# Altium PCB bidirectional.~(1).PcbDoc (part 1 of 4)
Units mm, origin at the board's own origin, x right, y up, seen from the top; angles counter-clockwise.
Board outline 190.5 x 127 mm, 6 copper layers (Top Layer, MidLayer1, MidLayer2, Mid-Layer 3, Mid-Layer 4, Bottom Layer), stack 2.997 mm thick; 416 components, 178 nets, 1084 pads, 2010 vias.
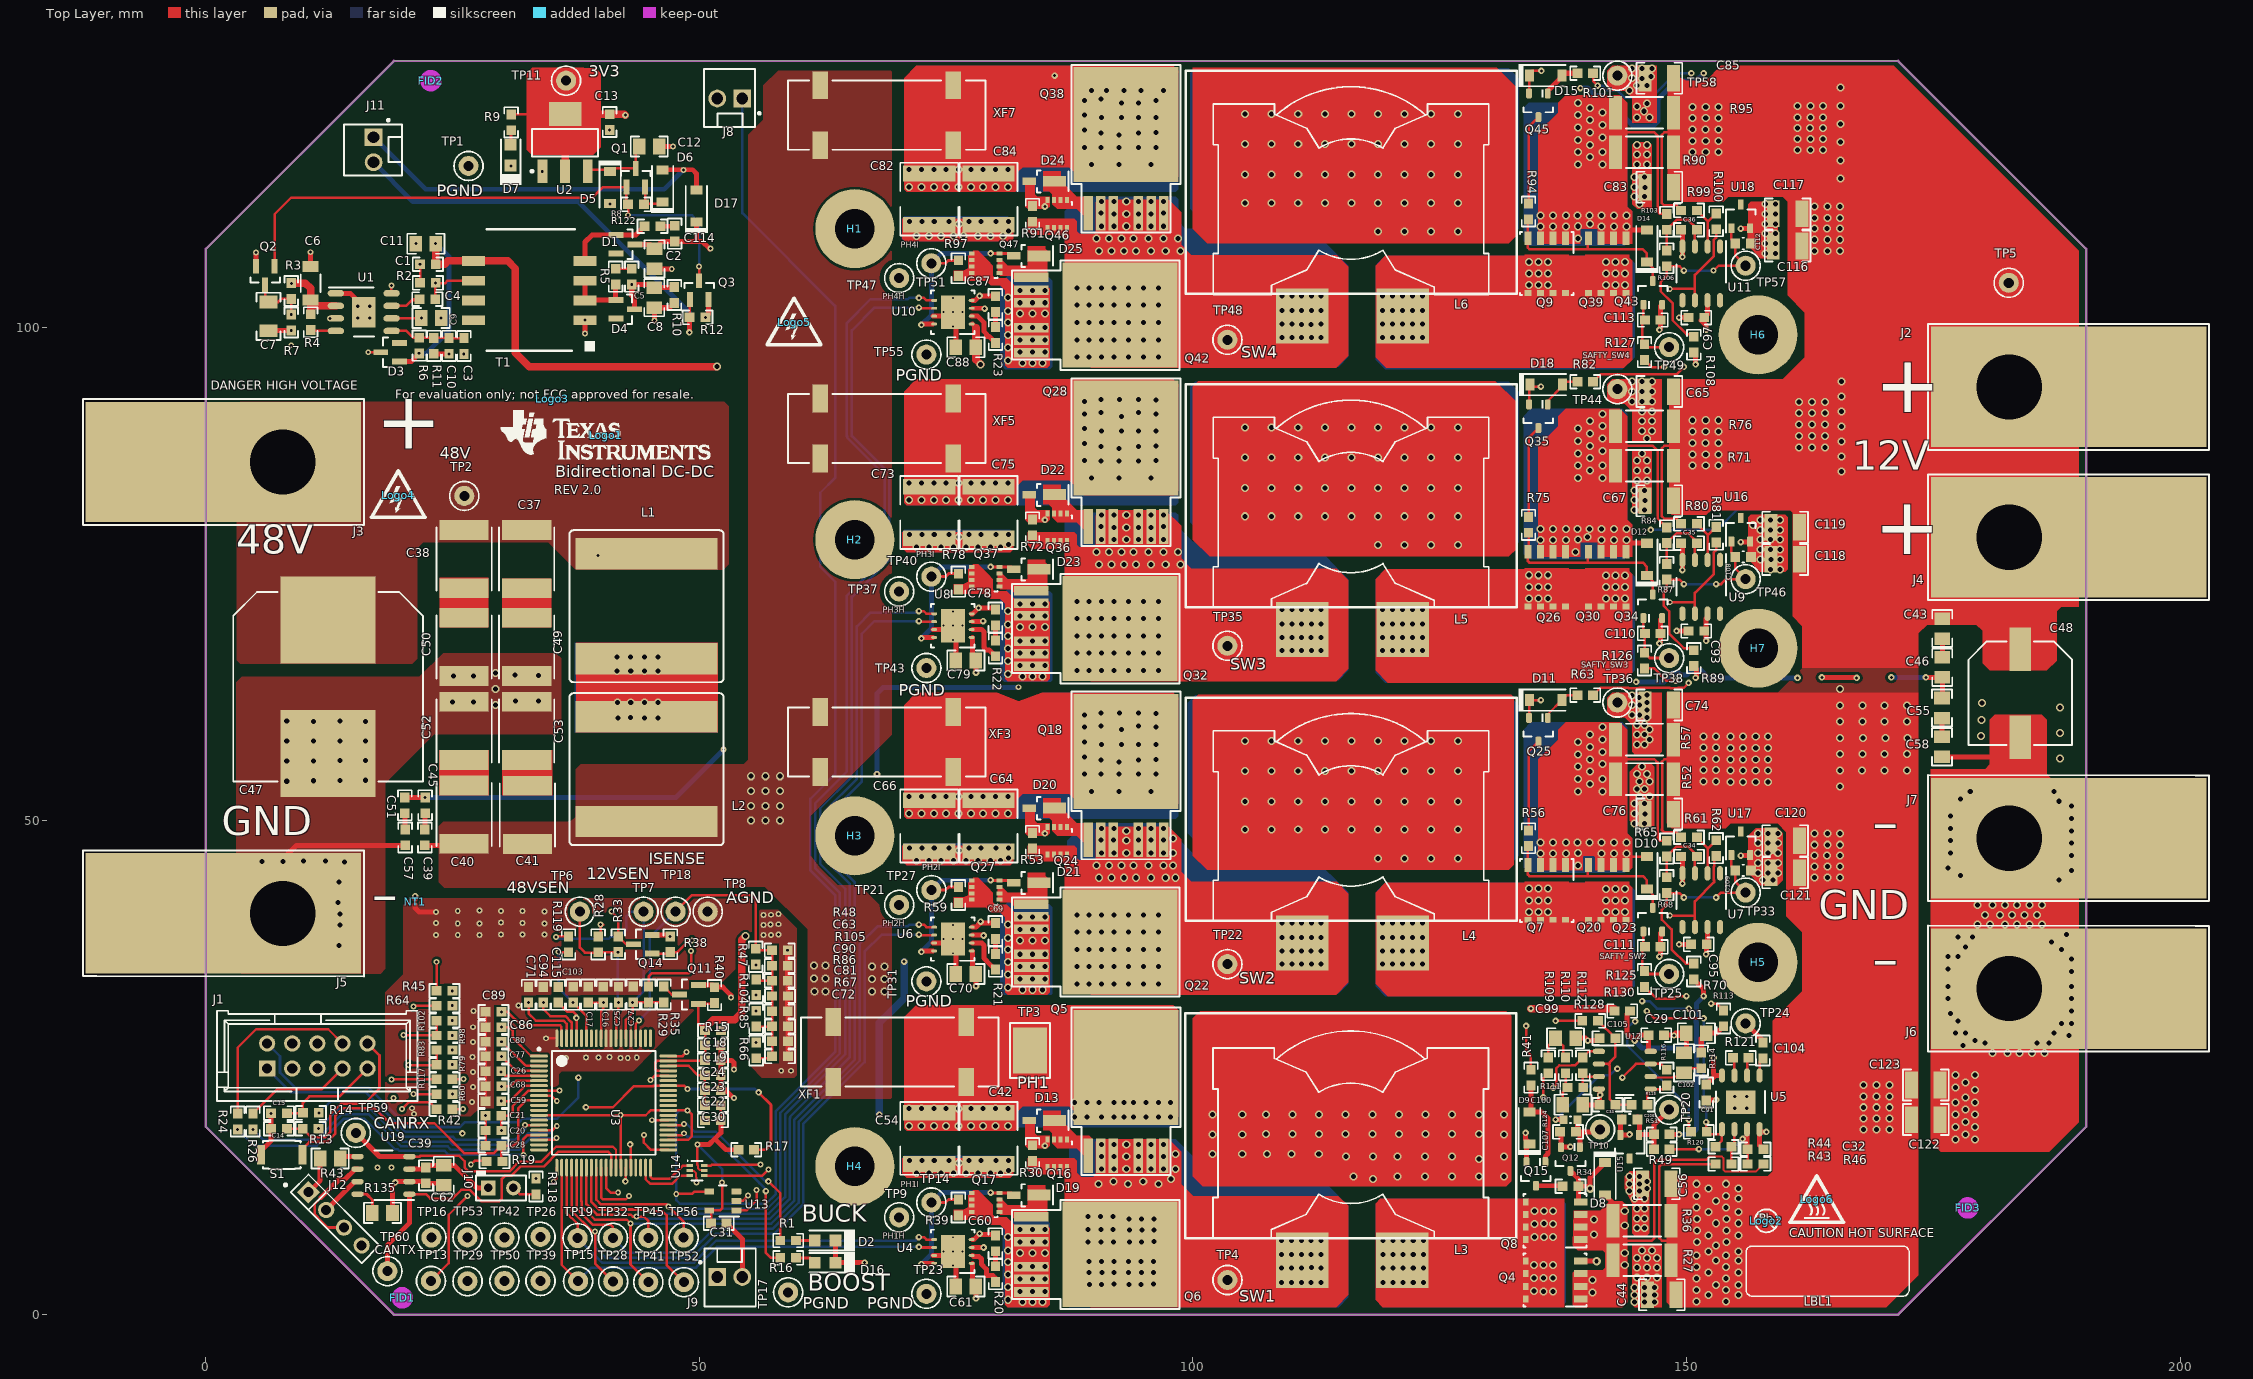
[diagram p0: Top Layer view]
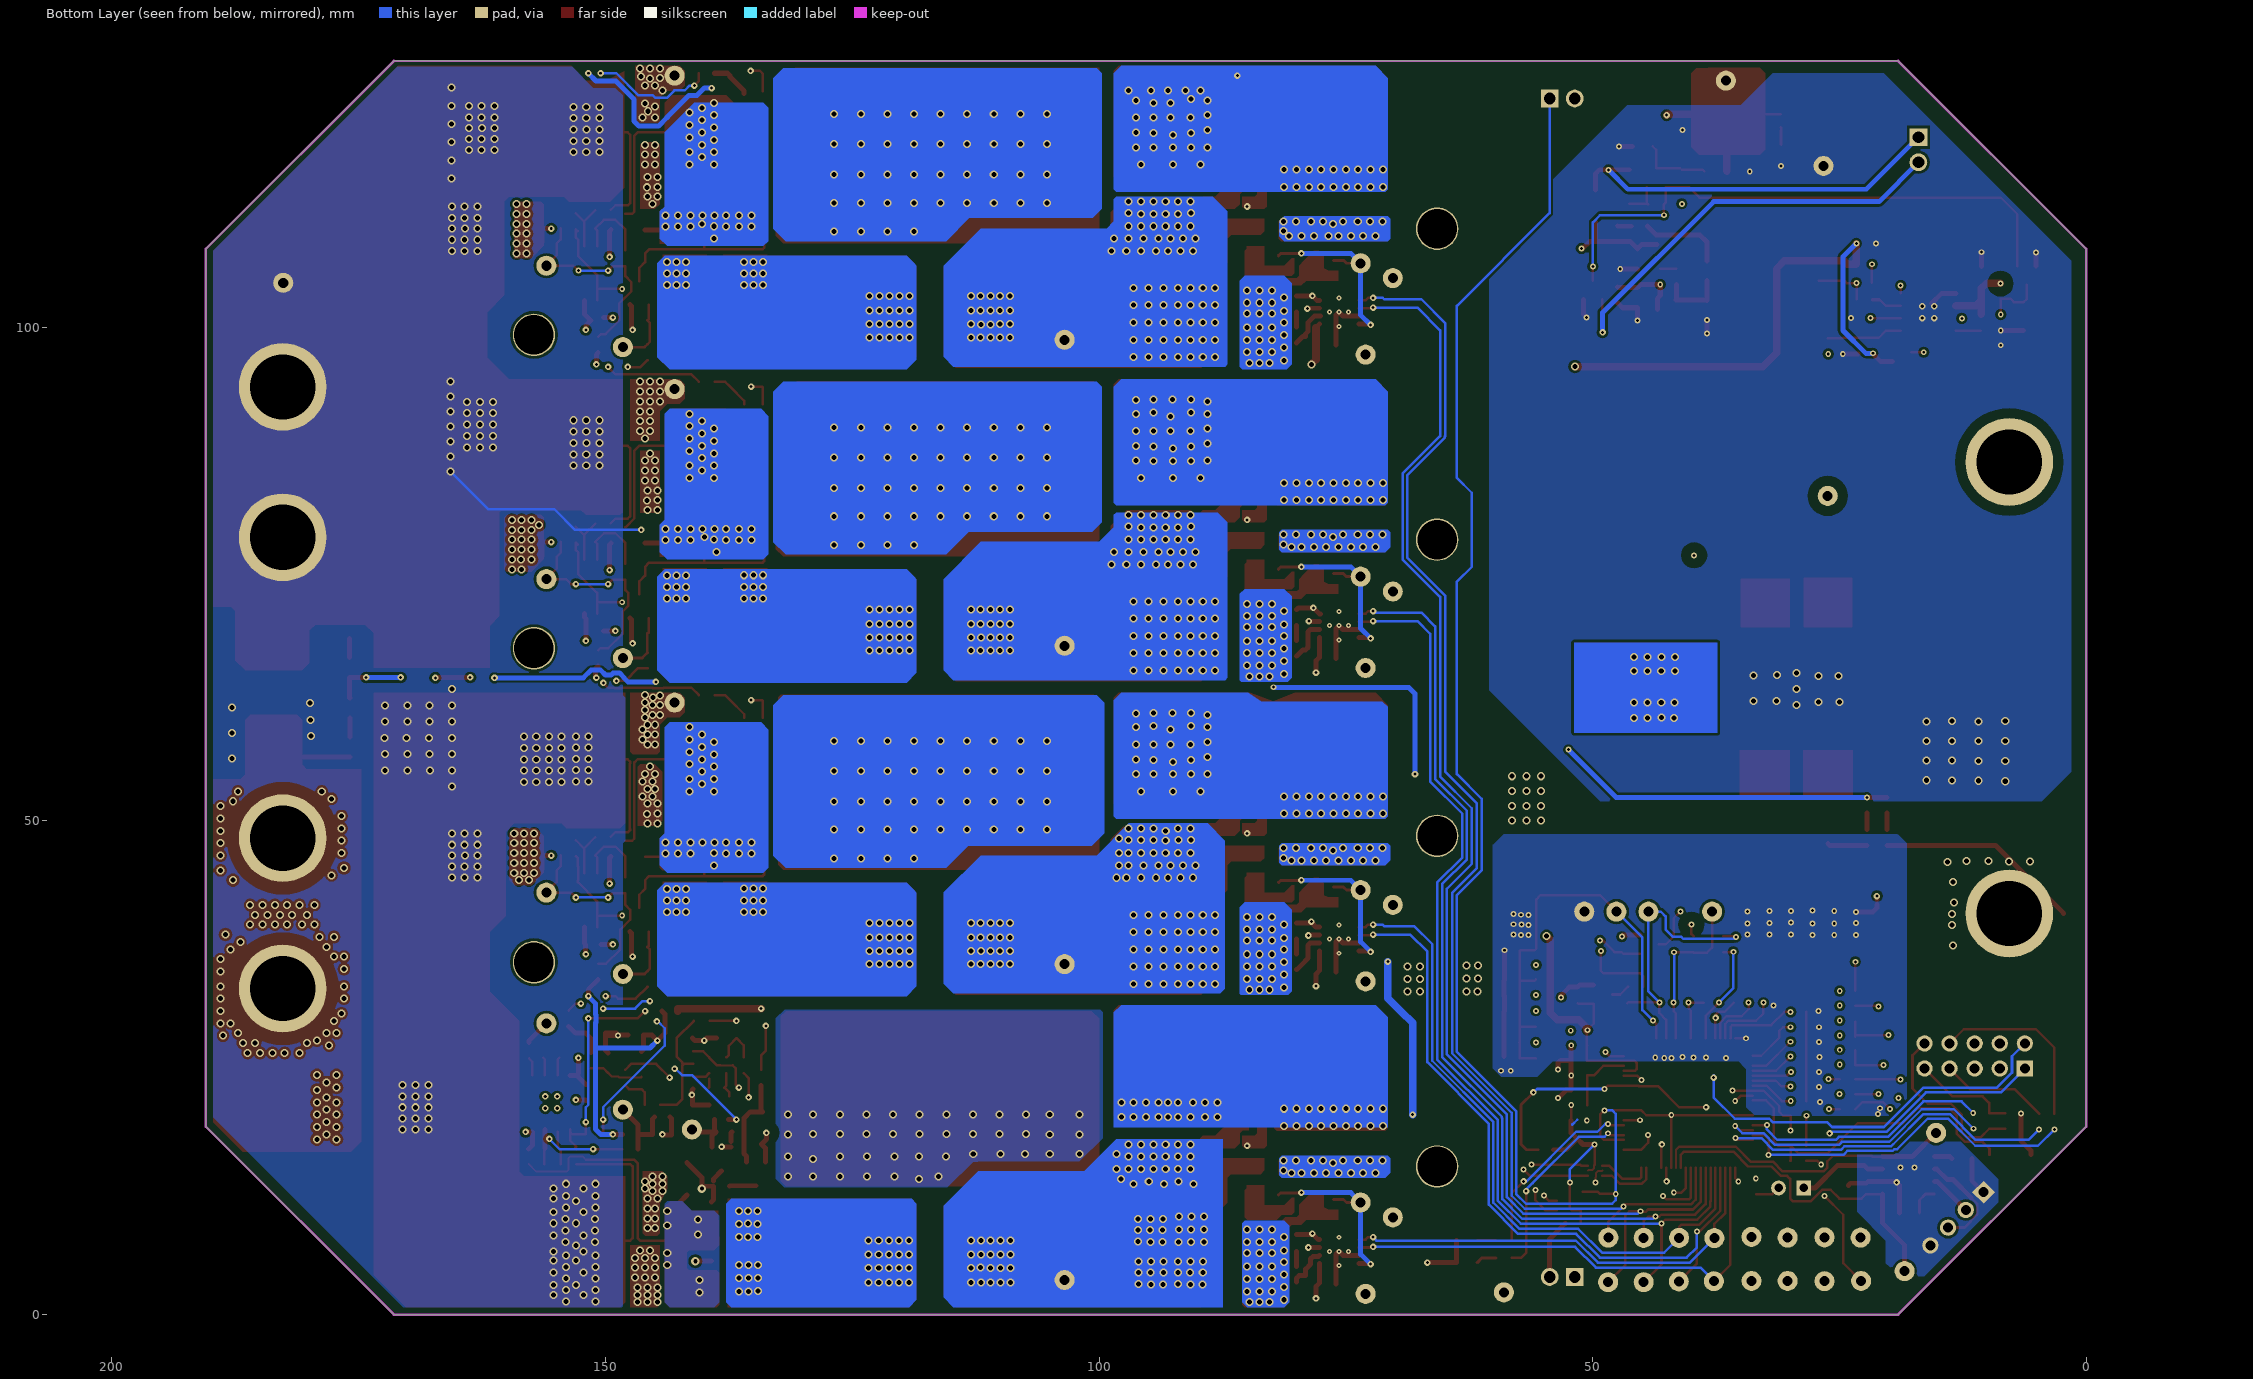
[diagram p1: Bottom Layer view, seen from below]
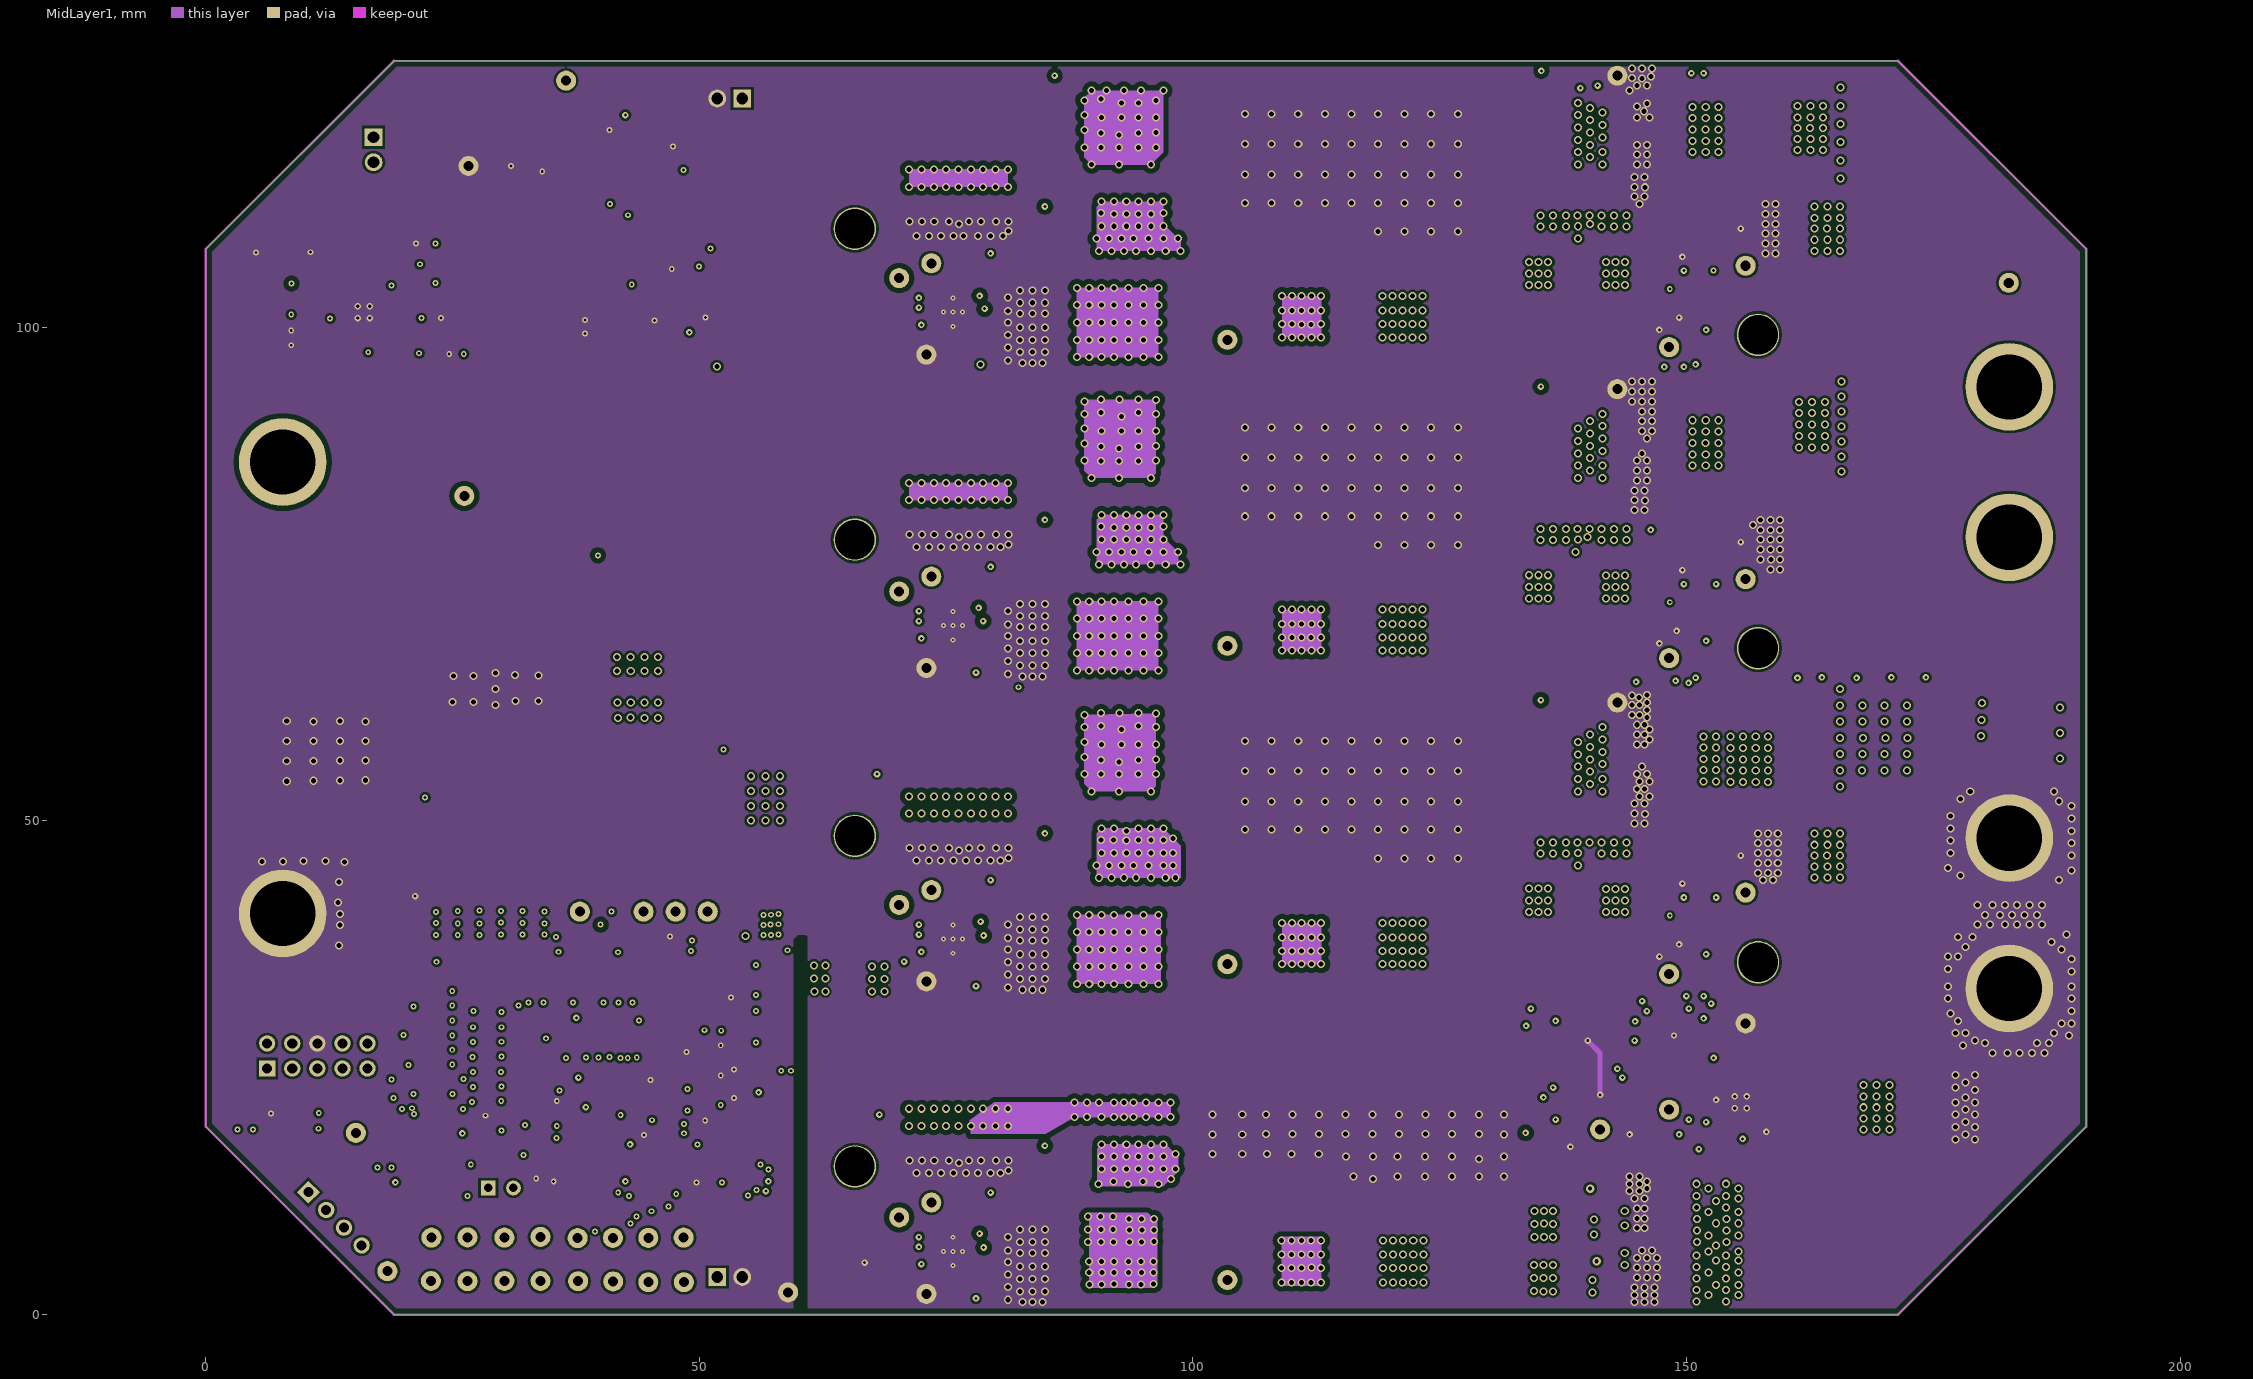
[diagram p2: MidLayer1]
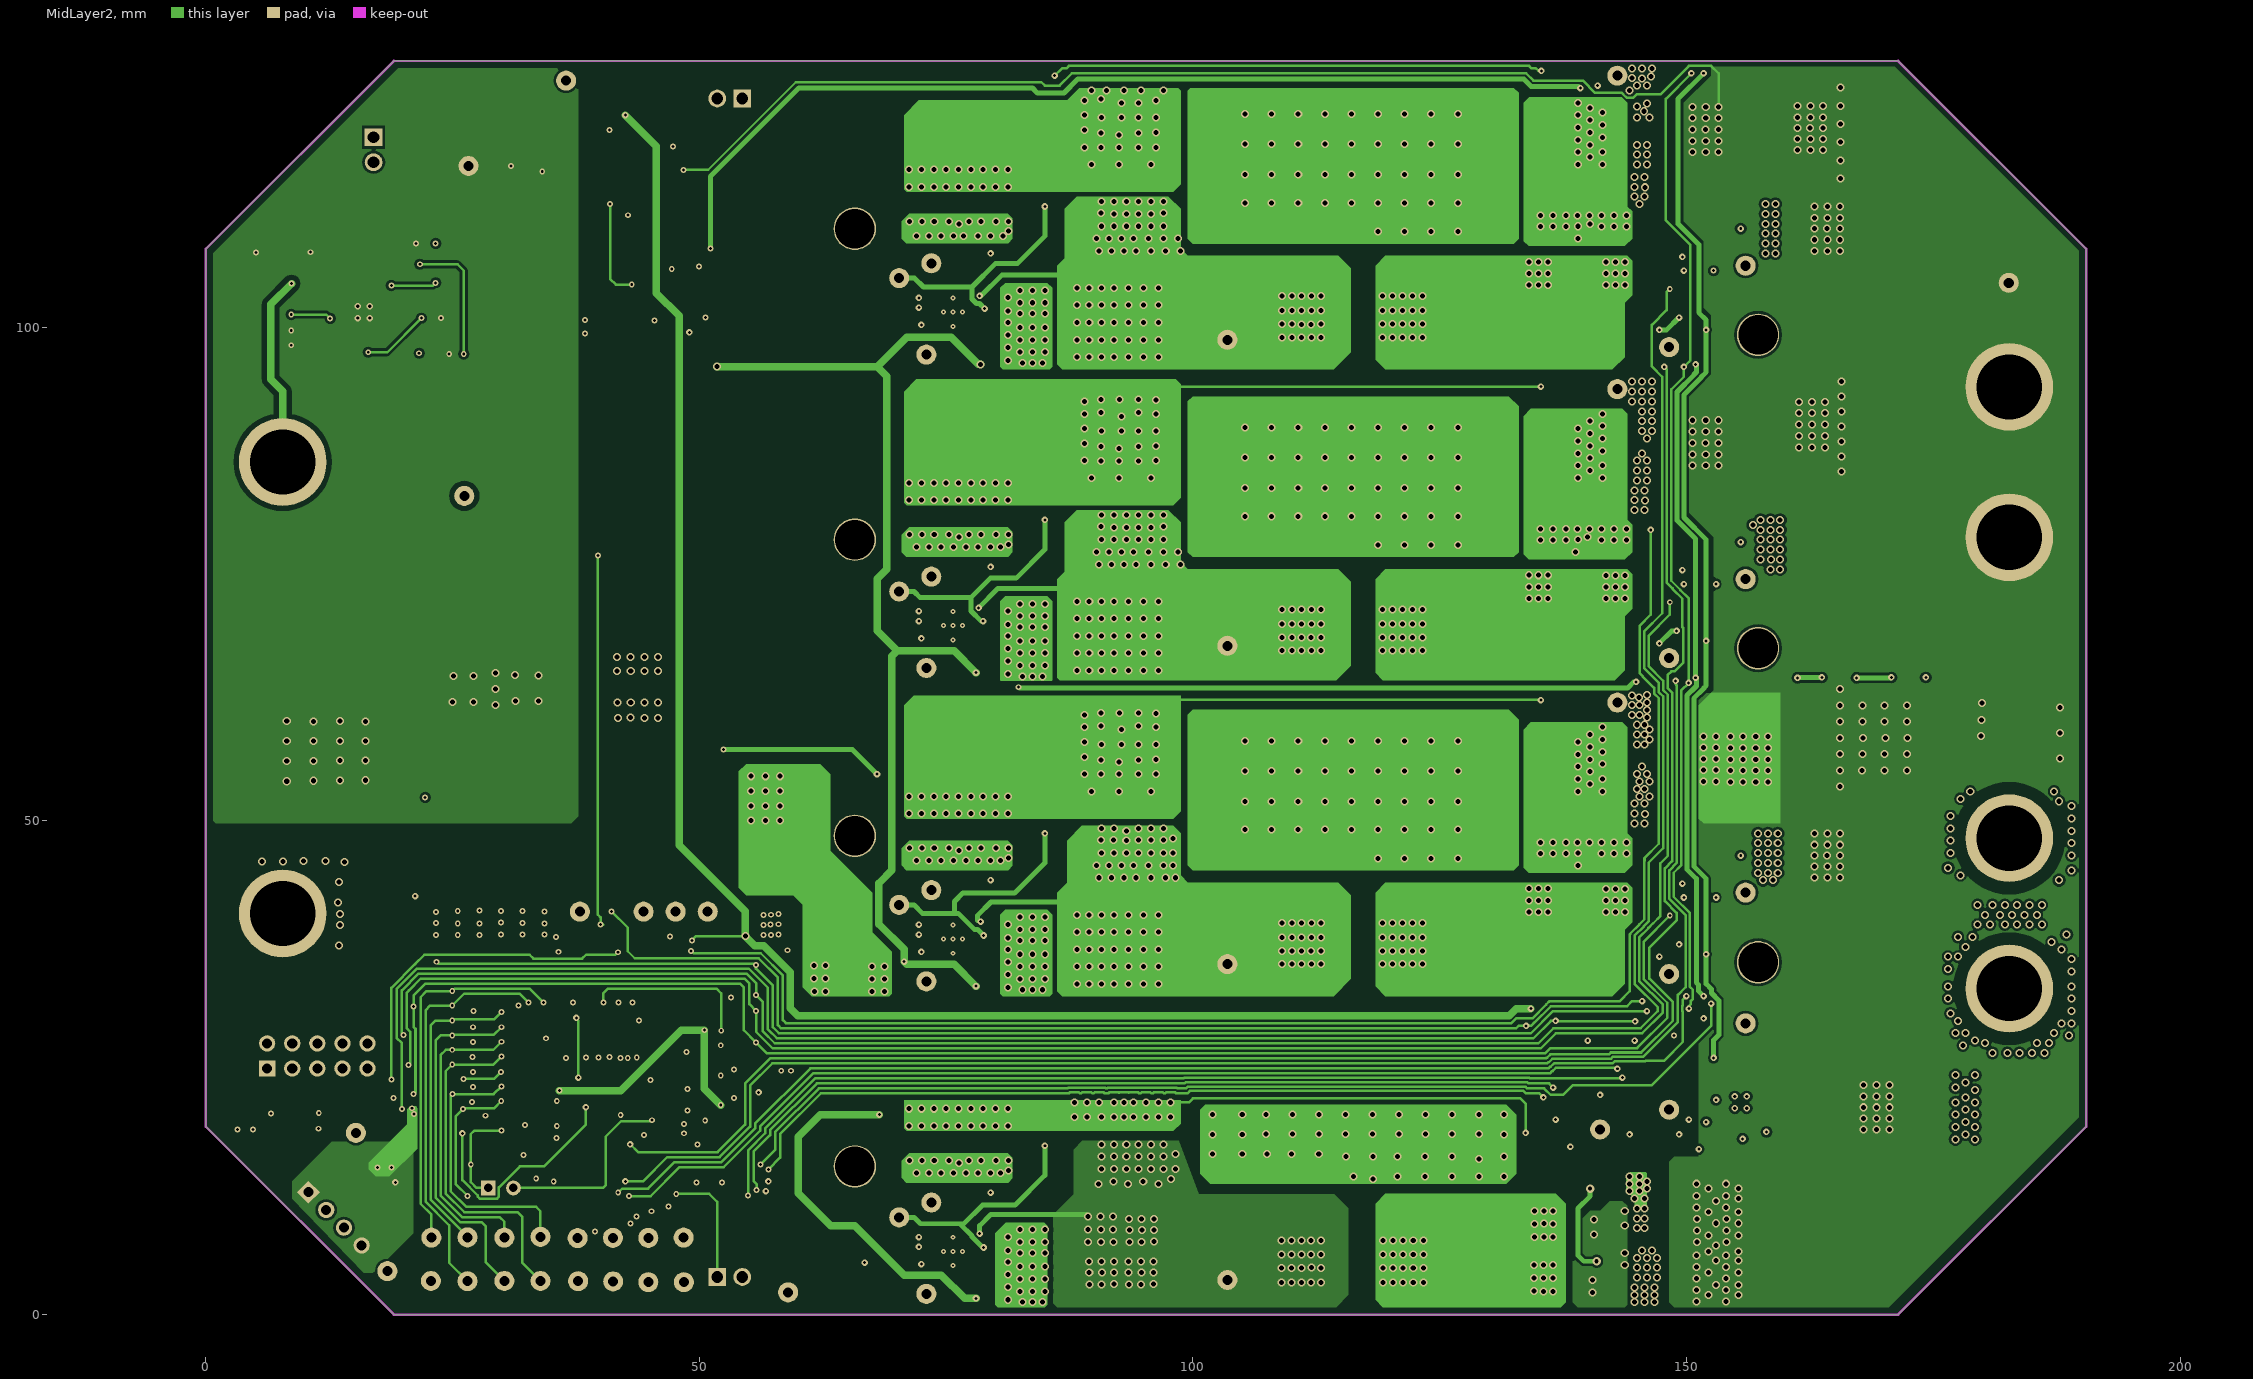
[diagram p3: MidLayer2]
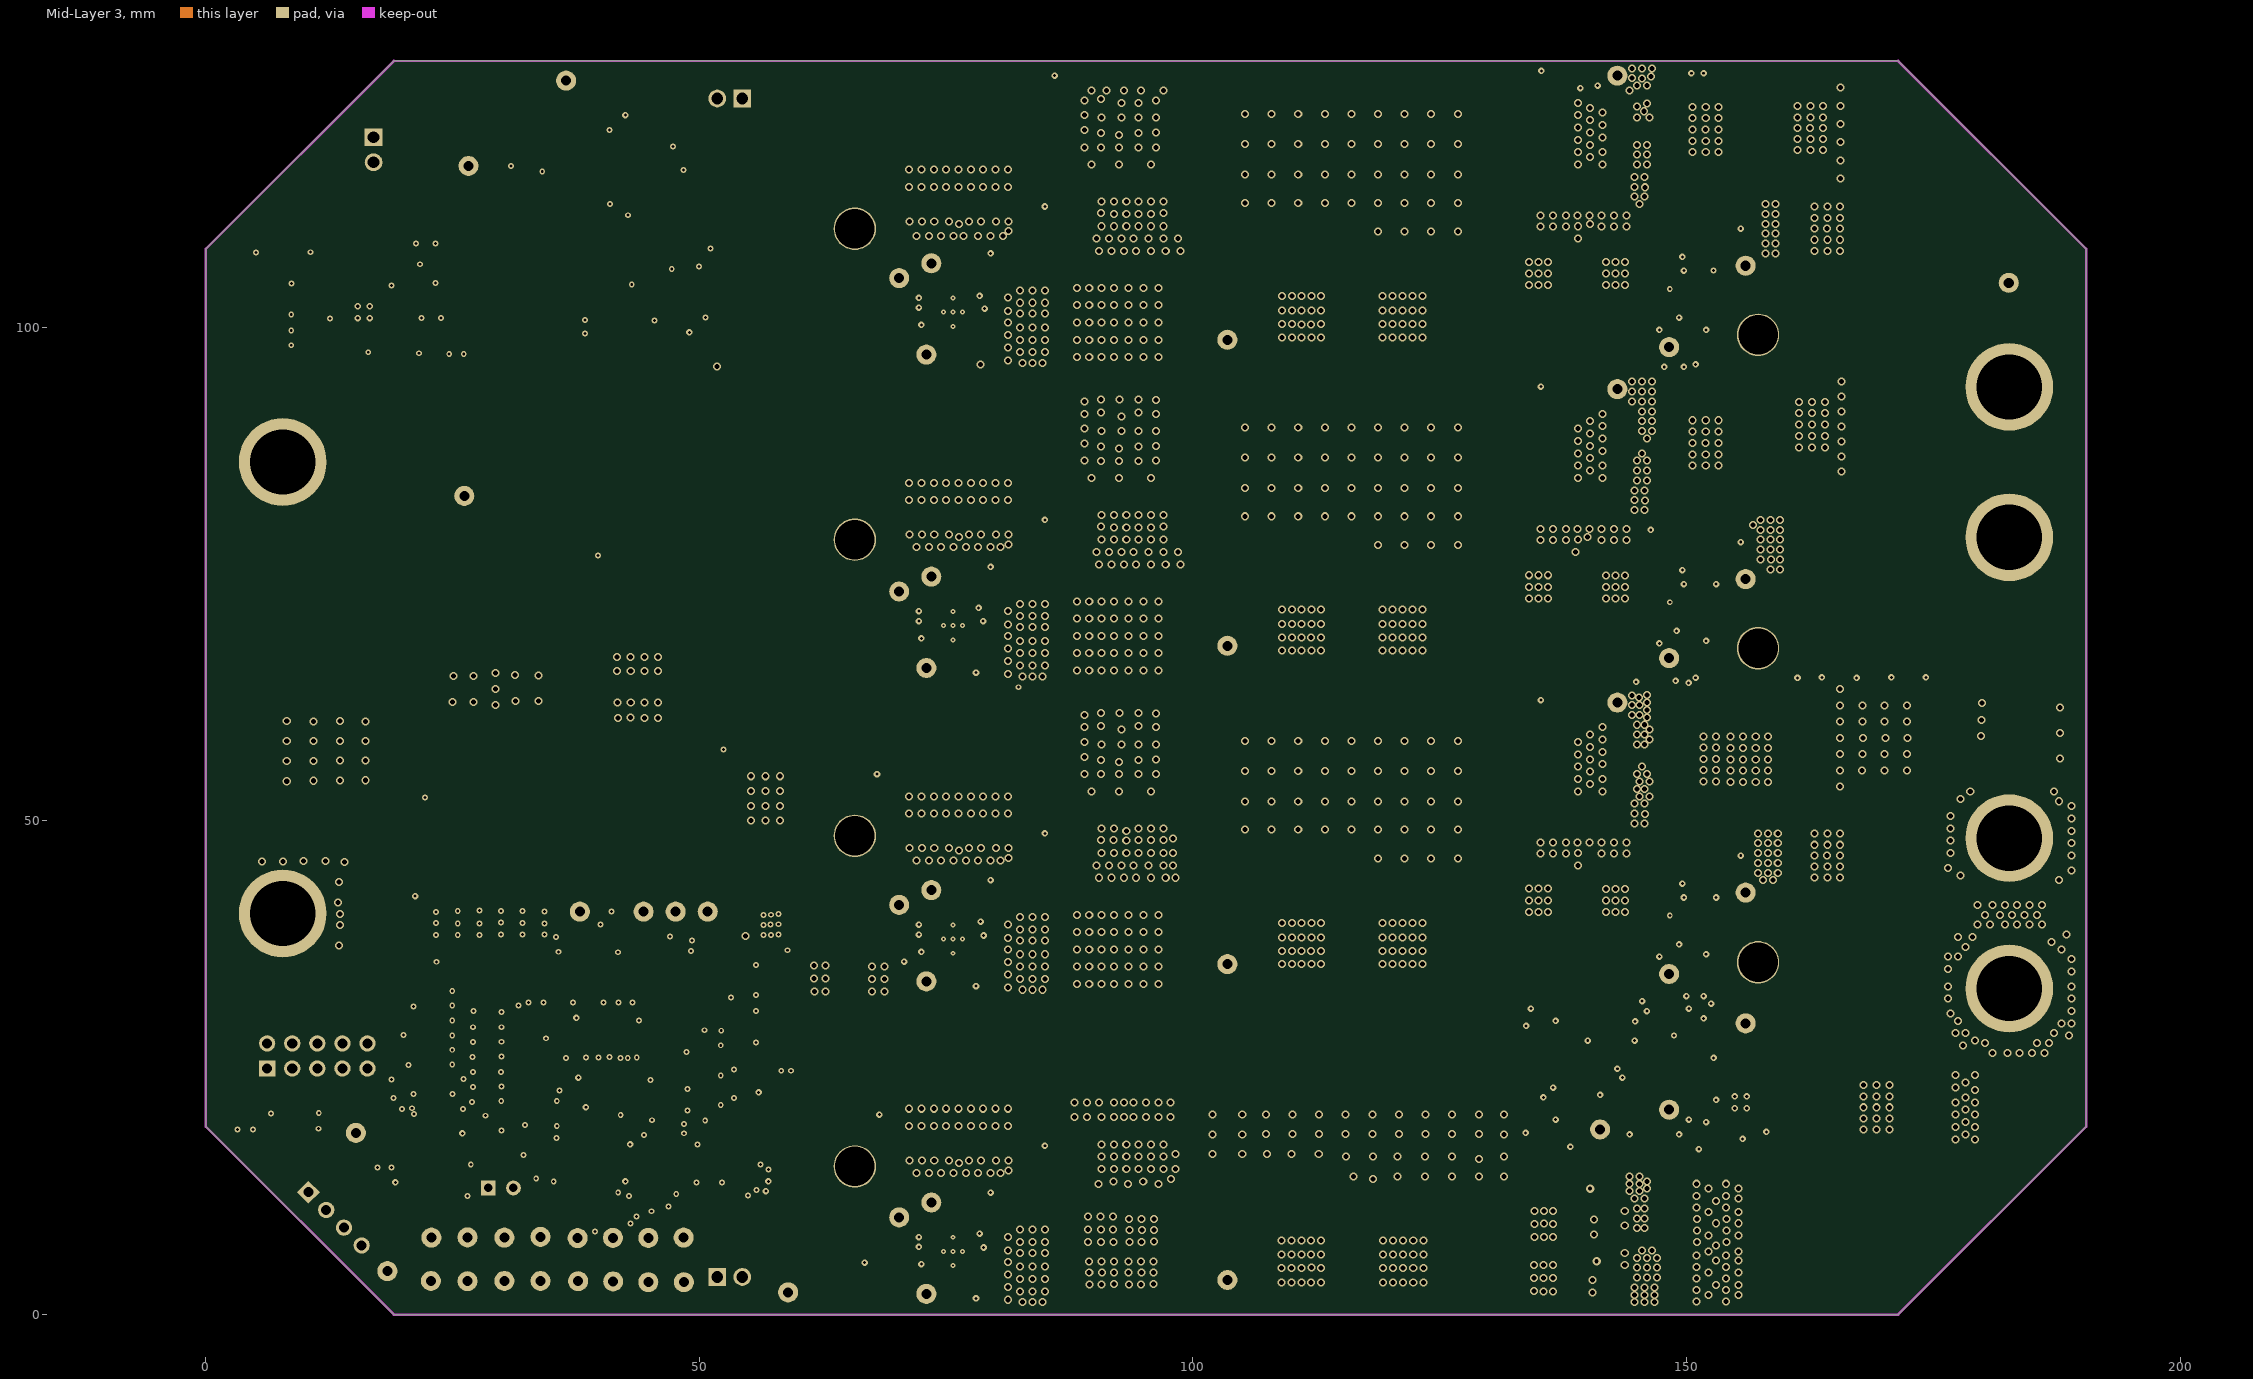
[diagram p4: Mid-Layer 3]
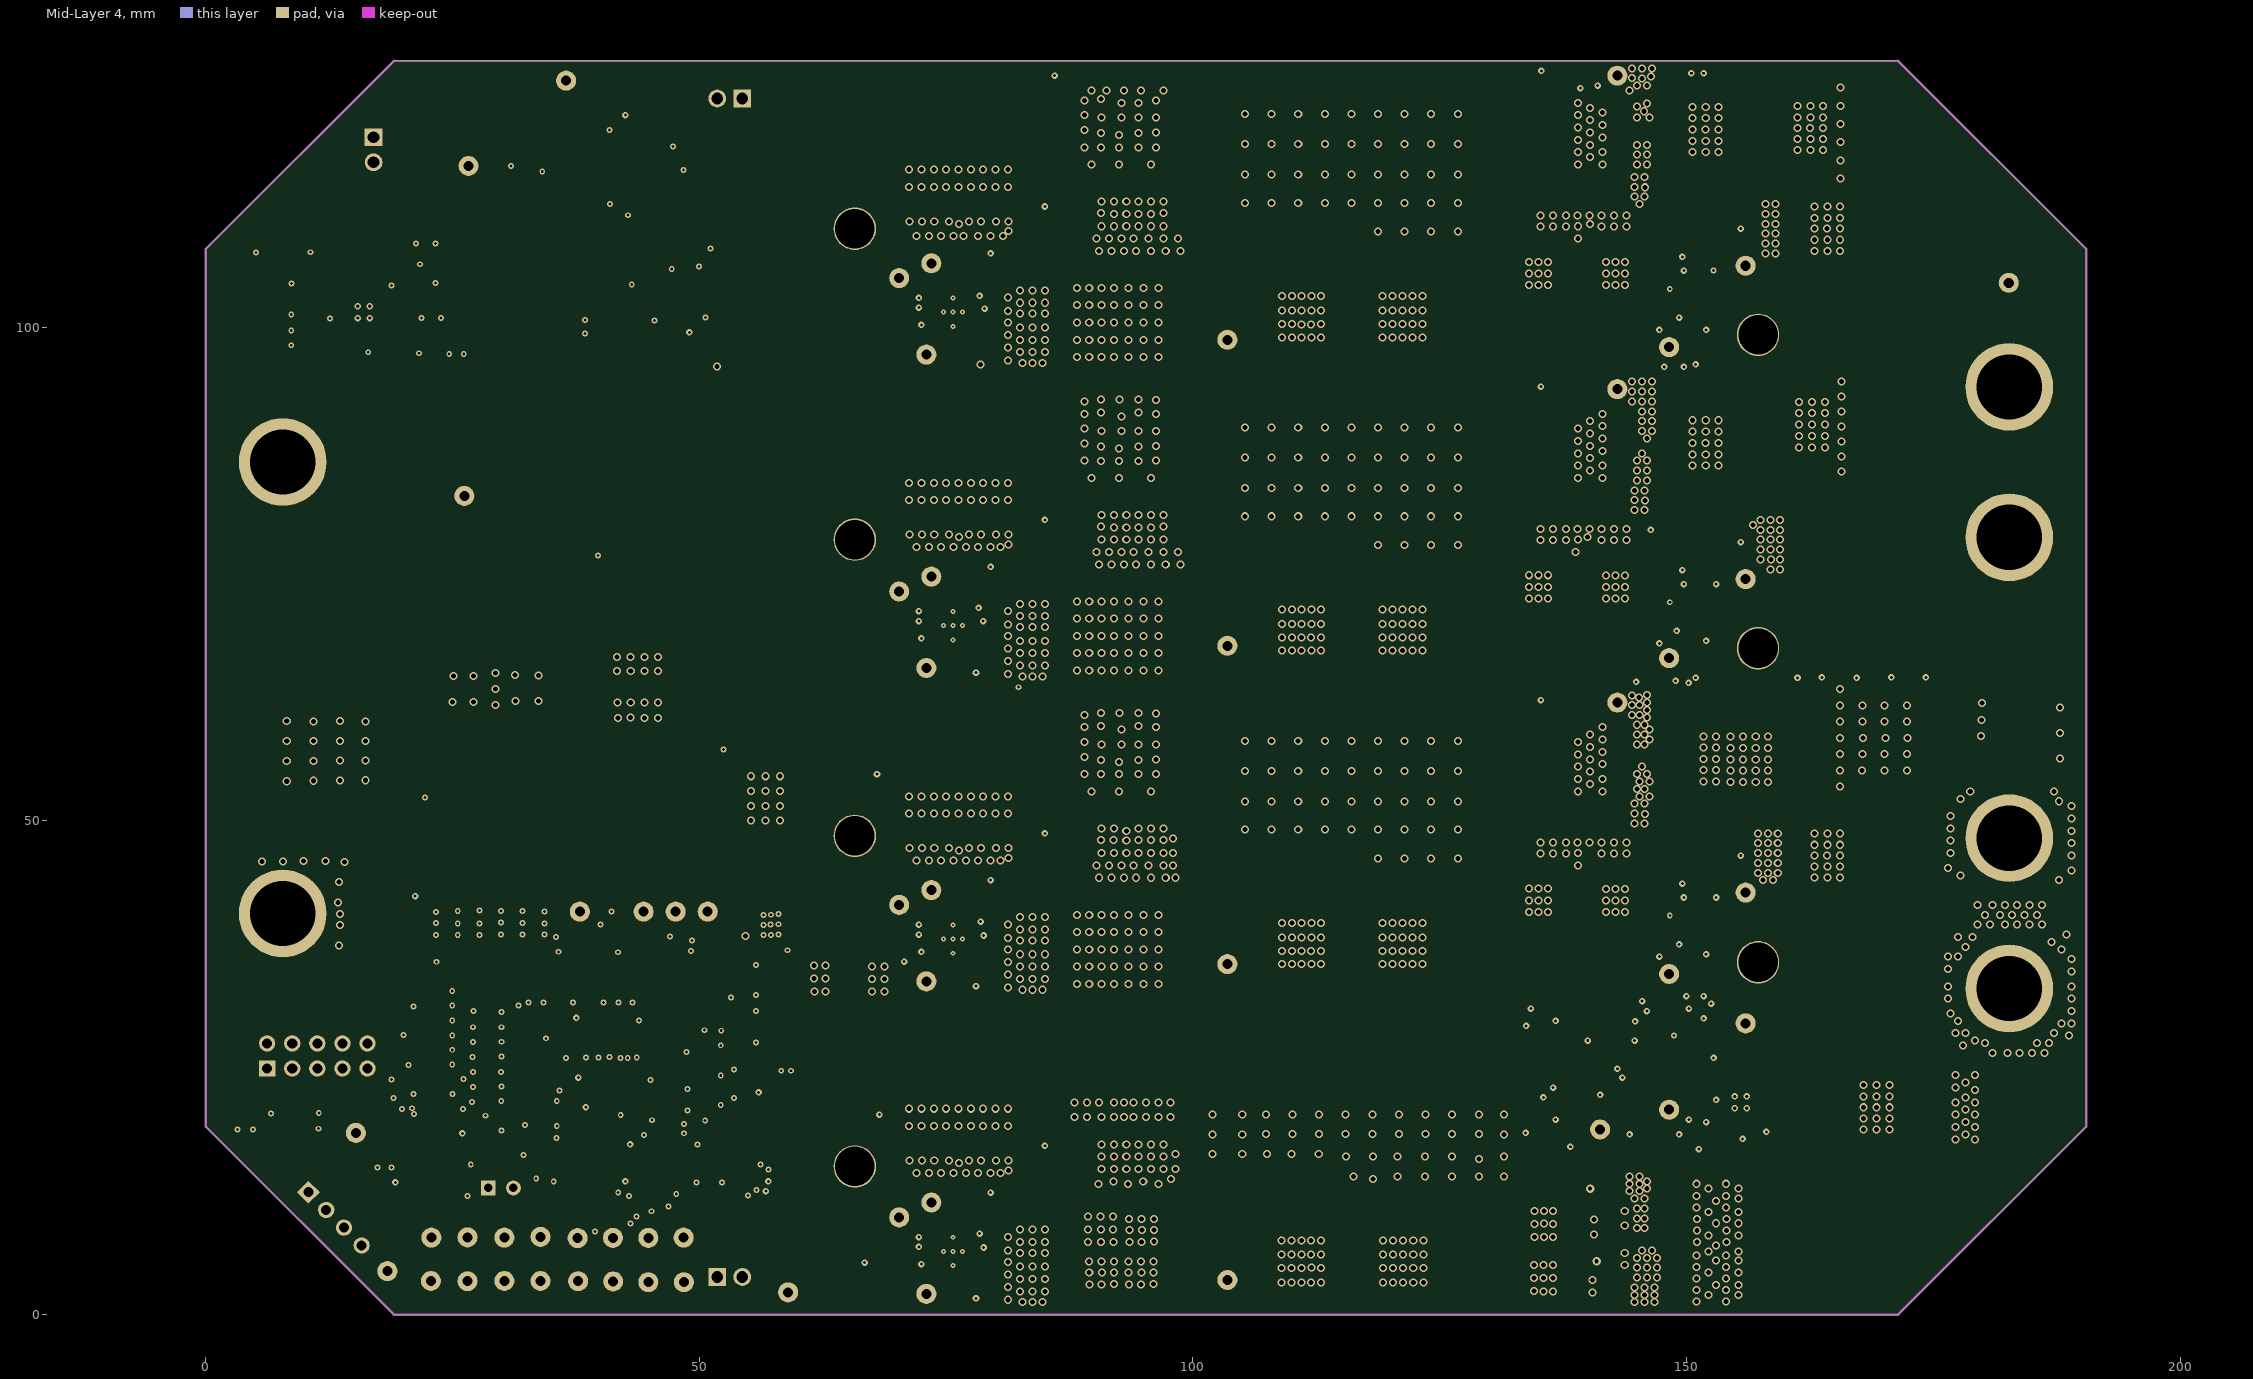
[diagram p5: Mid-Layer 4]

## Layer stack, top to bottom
Top Solder: solder mask 0.0102, Solder Resist, Dk 3.5
Top Layer: signal copper 0.0356
Dielectric1: core 1.5037, FR-4, Dk 4.8
MidLayer1: signal copper 0.0356
Dielectric2: prepreg 0.32, FR-4, Dk 4.8
MidLayer2: signal copper 0.0356
Dielectric3: core 0.32, FR-4, Dk 4.8
Mid-Layer 3: signal copper 0.0356
Dielectric4: dielectric 0.32, FR-4, Dk 4.8
Mid-Layer 4: signal copper 0.0356
Dielectric5: dielectric 0.32, FR-4, Dk 4.8
Bottom Layer: signal copper 0.0356
Bottom Solder: solder mask 0.0102, Solder Resist, Dk 3.5

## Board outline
0,19.05 19.05,0 171.45,0 190.5,19.05 190.5,107.95 171.45,127 19.05,127 0,107.95

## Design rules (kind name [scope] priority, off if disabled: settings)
AcuteAngle [All] p1 off: minimum=4.50000000000000E+0001 checktracksonly=FALSE
AssemblyTestPointUsage [All] p1 off: valid=2
AssemblyTestpoint [All] p1 off: testpointundercomponent=TRUE minsize=1.016 maxsize=2.54 preferedsize=1.524 minholesize=0 maxholesize=1.016 preferedholesize=0.813 testpointgrid=0.025 usegrid=TRUE gridtolerance=0 allowsidetop=TRUE allowsidebottom=TRUE
Clearance "1. HVvPGND Objs on Multilayer" [InNetClass('HV') And OnMultiLayer vs Not InNetClass('HV') And OnMultiLayer] p1: gap=1
Clearance "2a. HVvPGND Objs on Top" [InNetClass('HV') And OnTopLayer vs Not InNetClass('HV') And (OnTopLayer Or OnMultiLayer)] p2: gap=1
Clearance "2b. HVvPGND Objs on Bottom" [InNetClass('HV') And OnBottomLayer vs Not InNetClass('HV') And (OnBottomLayer Or OnMultiLayer)] p3: gap=1
Clearance "3a. HVvPGND Objs on Top" [Not InNetClass('HV') And OnTopLayer vs InNetClass('HV') And (OnTopLayer Or OnMultiLayer)] p4: gap=1
Clearance "3b. HVvPGND Objs on Bottom" [Not InNetClass('HV') And OnBottomLayer vs InNetClass('HV') And (OnBottomLayer Or OnMultiLayer)] p5: gap=1
Clearance "4. HVvPGND  Objs on Mid" [InNetClass('HV') And OnMid vs Not InNetClass('HV') And (OnMid Or OnMultiLayer)] p6: gap=0.5
Clearance "5. HVvPGND Objs on Mid" [Not InNetClass('HV') And OnMid vs InNetClass('HV') And (OnMid Or OnMultiLayer)] p7: gap=0.5
Clearance Clearance_BoardEdge_MountingHoles [OnCopper and InComponentClass('Mounting Holes') vs IsKeepOut] p8: gap=1.016
Clearance Clearance_BoardEdge_Poly [OnCopper and InPoly vs OnLayer('Keep-Out Layer')] p9: gap=0.5
Clearance Clearance_Poly [InPolygon] p10: gap=0.25
Clearance [OnCopper vs OnCopper] p11: gap=0.199
ComponentClearance ComponentClearance_Shunt [InComponentClass('Header') vs InComponentClass('Shunt')] p1: gap=0 collisioncheckmode=3 verticalgap=0 showdistances=FALSE
ComponentClearance ComponentClearance_Logo [InComponentClass('Logo')] p2: gap=0.25 collisioncheckmode=3 verticalgap=0 showdistances=FALSE
ComponentClearance ComponentClearance_ScrewToNut [(HasFootprint('NY PMS 440 0025 PH')) vs (HasFootprint('Keystone_1902C'))] p3: gap=0.127 collisioncheckmode=3 verticalgap=0.254 showdistances=FALSE
ComponentClearance ComponentClearance_MountingHoles [InComponentClass('Mounting Holes')] p4: gap=0.1 collisioncheckmode=3 verticalgap=0 showdistances=FALSE
ComponentClearance ComponentClearance_SmallPassives [HasFootprint('0201*') or HasFootprint('0402*') or HasFootprint('0508') or HasFootprint('0603*') or HasFootprint('0612') or HasFootprint('0805*') or HasFootprint('0815*') or HasFootprint('0830*') or HasFootprint('1206*') or HasFootprint('1210*') or HasFootprint('1808*') or HasFootprint('1812*') or HasFootprint('1825*') or HasFootprint('2010*') or HasFootprint('2220*') or HasFootprint('2225*') or HasFootprint('2512*') or HasFootprint('2728*') or HasFootprint('3518*') vs HasFootprint('0201*') or HasFootprint('0402*') or HasFootprint('0508') or HasFootprint('0603*') or HasFootprint('0612') or HasFootprint('0805*') or HasFootprint('0815*') or HasFootprint('0830*') or HasFootprint('1206*') or HasFootprint('1210*') or HasFootprint('1808*') or HasFootprint('1812*') or HasFootprint('1825*') or HasFootprint('2010*') or HasFootprint('2220*') or HasFootprint('2225*') or HasFootprint('2512*') or HasFootprint('2728*') or HasFootprint('3518*')] p5: gap=0.05 collisioncheckmode=3 verticalgap=0.02 showdistances=FALSE
ComponentClearance ComponentClearance_THtoSMT [IsThruComponent vs IsSMTComponent] p6: gap=0.1 collisioncheckmode=3 verticalgap=0.1 showdistances=FALSE
ComponentClearance ComponentClearance_THtoTH [IsThruComponent vs IsThruComponent] p7: gap=0.1 collisioncheckmode=3 verticalgap=0.1 showdistances=FALSE
ComponentClearance [All] p8: gap=0.05 collisioncheckmode=3 verticalgap=0 showdistances=FALSE
DiffPairsRouting [All] p1 off: maxlimit=2.54 minlimit=0.254 mostfreqgap=0.254 toplayer_minwidth=0.381 toplayer_maxwidth=0.381 toplayer_prefwidth=0.381 midlayer1_minwidth=0.381 midlayer1_maxwidth=0.381 midlayer1_prefwidth=0.381 midlayer2_minwidth=0.381 midlayer2_maxwidth=0.381 midlayer2_prefwidth=0.381 midlayer3_minwidth=0.381 midlayer3_maxwidth=0.381 midlayer3_prefwidth=0.381 midlayer4_minwidth=0.381 midlayer4_maxwidth=0.381 midlayer4_prefwidth=0.381 bottomlayer_minwidth=0.381 bottomlayer_maxwidth=0.381 bottomlayer_prefwidth=0.381 maxuncoupledlength=25.4
FabricationTestPointUsage TestPointUsage [All] p1 off: valid=2 allowmultiple=FALSE
FabricationTestpoint Testpoint [All] p1 off: side=3 testpointundercomponent=TRUE minsize=1.016 maxsize=2.54 preferedsize=1.524 minholesize=0 maxholesize=1.016 preferedholesize=0.813 testpointgrid=0.025 allowsidetop=TRUE allowsidebottom=TRUE usegrid=TRUE gridtolerance=0
FanoutControl Fanout_LCC [IsLCC] p1 off: bgadir=Out bgaviamode=Centered fanoutstyle=Auto fanoutdirection=Alternating viagrid=0.025 // Fanout_LCC (Default Rule)
FanoutControl Fanout_BGA [IsBGA] p2 off: bgadir=Out bgaviamode=Centered fanoutstyle=Auto fanoutdirection=Alternating viagrid=0.025 // Fanout_BGA (Default Rule)
FanoutControl Fanout_SOIC [IsSOIC] p3 off: bgadir=Out bgaviamode=Centered fanoutstyle=Auto fanoutdirection=Alternating viagrid=0.025 // Fanout_SOIC (Default Rule)
FanoutControl Fanout_Default [All] p4 off: bgadir=Out bgaviamode=Centered fanoutstyle=Auto fanoutdirection=Alternating viagrid=0.025 // Fanout_Default (Default Rule)
FanoutControl Fanout_Small [(CompPinCount < 5)] p5 off: bgadir=Out bgaviamode=Centered fanoutstyle=Auto fanoutdirection=OutThenIn viagrid=0.025 // Fanout_Small (Default Rule)
Height [All] p1 off: minheight=0 maxheight=25.4 prefheight=12.7
HoleSize [All] p1: absolutevalues=TRUE maxlimit=7 minlimit=0.2 maxpercent=80.000 minpercent=20.000
HoleToHoleClearance [All] p1: gap=0.199 allowstackedmicrovias=TRUE
LayerPairs [All] p1 off: enforce=TRUE
MinimumAnnularRing MinimumAnnularRing_ThermalPadVias [IsVia and InAnyComponent] p1: minimumring=0.149
MinimumAnnularRing [All] p2: minimumring=0.149
MinimumSolderMaskSliver MinimumSolderMaskSliver_Logo [InComponentClass('Logo') vs InComponentClass('Logo')] p1: minsoldermaskwidth=0.018
MinimumSolderMaskSliver [All] p2 off: minsoldermaskwidth=0.04
PlaneClearance [All] p1 off: clearance=0.381
PlaneConnect PlaneConnect_1 [All] p1 off: planeconnectstyle=Direct reliefexpansion=0.508 reliefentries=4 reliefconductorwidth=0.254 reliefairgap=0.254
PlaneConnect [ISVIA] p2 off: planeconnectstyle=Direct reliefexpansion=0.254 reliefentries=4 reliefconductorwidth=0.254 reliefairgap=0.254
PolygonConnect PolygonConnect_1 [All vs isvia] p1: connectstyle=Direct reliefconductorwidth=0.254 reliefentries=4 polygonreliefangle="90 Angle" airgapwidth=0.254
PolygonConnect [All] p2: connectstyle=Direct reliefconductorwidth=0.254 reliefentries=4 polygonreliefangle="90 Angle" airgapwidth=0.254
RoutingLayers [All] p1 off: top layer_v5=TRUE mid layer 1_v5=TRUE mid layer 2_v5=TRUE mid layer 3_v5=FALSE mid layer 4_v5=FALSE bottom layer_v5=TRUE
RoutingPriority [All] p1 off: routingpriority=0
RoutingTopology [All] p1 off: topology=Shortest
RoutingVias [All] p1: holewidth=0.3 width=0.6 viastyle="Through Hole" minholewidth=0.2 minwidth=0 maxholewidth=1 maxwidth=1.5
SilkToBoardRegionClearance [All] p1 off:
SilkToSilkClearance [All] p1: silktosilkclearance=0
SilkToSolderMaskClearance SilkscreenOverComponentPads [IsPad] p1: minsilkscreentomaskgap=0 clearancetoexposedcopper=TRUE
SolderMaskExpansion [All] p1: expansion=0.05
UnpouredPolygon [All] p1: allowunpoured=FALSE
Width [All] p1: maxlimit=2.54 minlimit=0.2 preferedwidth=0.5 checkconnectedcopper=TRUE
5 further rules are at their usual default settings.

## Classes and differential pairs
net class HV: BAT_48V NetD13_1 NetD20_1 NetD22_1 NetD24_1 PH1_H PH2_H PH3_H PH4_H PHASE1 PHASE2 PHASE3 PHASE4 SW1 SW2 SW3 SW4
component class "Aux Power Supply": C1 C2 C3 C4 C5 C6 C7 C8 C9 C10 C11 C12 C13 C114 D1 D3 D4 D5 D6 D7 D17 J11 Q1 Q2 Q3 R2 R3 R4 R5 R6 R7 R8 R9 R10 R11 R12 R122 T1 TP1 U1 U2
component class bidirectional-MCU: C14 C15 C16 C17 C18 C19 C20 C21 C22 C23 C24 C25 C26 C27 C28 C39 C62 C103 C115 D2 D16 J1 J8 J9 J10 J12 NT1 R1 R13 R14 R15 R16 R17 R19 R24 R26 R43 R117 R118 R119 R124 R125 R126 R127 R135 S1 TP8 TP17 TP59 TP60 U3 U19
component class bidirectional-Phase4: C36 C82 C83 C84 C85 C86 C87 C88 C89 C90 C97 C112 C113 D14 D15 D24 D25 L6 Q9 Q38 Q39 Q42 Q43 Q45 Q46 Q47 R23 R90 R91 R94 R95 R97 R98 R99 R100 R101 R102 R103 R104 R105 R106 R107 R108 TP47 TP48 TP49 TP50 TP51 TP52 TP53 TP55 TP56 TP57 TP58 U10 U11 U18 XF7
component class bidirectional-phase1: C29 C30 C31 C32 C33 C37 C38 C39 C40 C41 C42 C43 C44 C45 C46 C47 C48 C49 C50 C51 C52 C53 C54 C55 C56 C57 C58 C59 C60 C61 C63 C91 C94 C99 C100 C101 C102 C104 C105 C106 C107 C116 C117 C118 C119 C120 C121 C122 C123 D8 D9 D13 D19 J2 J3 J4 J5 J6 J7 L1 L2 L3 Q4 Q5 Q6 Q8 Q11 Q12 Q14 Q15 Q16 Q17 R20 R27 R28 R29 R30 R33 R34 R35 R36 R38 R39 R40 R41 R42 R43 R44 R45 R46 R47 R48 R49 R51 R109 R110 R111 R112 R113 R114 R115 R116 R120 R121 R128 R130 TP2 TP3 TP4 TP5 TP6 TP7 TP9 TP10 TP11 TP13 TP14 TP15 TP16 TP18 TP19 TP20 TP23 TP24 U4 U5 U12 U13 U14 U15 XF1
component class bidirectional-Phase2&3: C34 C35 C64 C65 C66 C67 C68 C69 C70 C71 C72 C73 C74 C75 C76 C77 C78 C79 C80 C81 C93 C95 C108 C109 C110 C111 D10 D11 D12 D18 D20 D21 D22 D23 L4 L5 Q7 Q18 Q20 Q22 Q23 Q24 Q25 Q26 Q27 Q28 Q30 Q32 Q34 Q35 Q36 Q37 R21 R22 R52 R53 R56 R57 R59 R60 R61 R62 R63 R64 R65 R66 R67 R68 R70 R71 R72 R75 R76 R78 R79 R80 R81 R82 R83 R84 R85 R86 R87 R89 TP21 TP22 TP25 TP26 TP27 TP28 TP29 TP31 TP32 TP33 TP35 TP36 TP37 TP38 TP39 TP40 TP41 TP42 TP43 TP44 TP45 TP46 U6 U7 U8 U9 U16 U17 XF3 XF5
component class AssemblyNote: ZZ1 ZZ2 ZZ3 ZZ4
component class FiducialMark: FID1 FID2 FID3
component class Hardware_ANSI-B: !PCB FID1 FID2 FID3 H1 H2 H3 H4 H5 H6 H7 LBL1 Logo1 Logo2 Logo3 Logo4 Logo5 Logo6 ZZ1 ZZ2 ZZ3 ZZ4
component class Header: J12
component class Label: LBL1
component class Logo: Logo1 Logo4 Logo5 Logo6
component class "Mounting Holes": H1 H2 H3 H4 H5 H6 H7

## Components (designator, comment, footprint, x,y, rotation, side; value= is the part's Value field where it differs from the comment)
C1 "06031C332JAT2A" 0603 22.504,106.401 r180 top
C2 "0805YD106MAT2A" 0805_HV 45.466,106.947 r270 top
C3 "06035C104KAT2A" 0603 26.162,98.12 r90 top
C4 "06033C104JAT2A" 0603 22.454,102.87 r180 top
C5 "C0603C101J5GAC" 0603 43.155,105.143 r90 top
C6 "GRM31CR72A225KA73L" 1206_190 10.617,104.47 r90 top
C7 "C3216X7R2A474K" 1206 6.35,101.117 r270 top
C8 "0805YD106MAT2A" 0805_HV 45.441,103.01 r270 top
C9 "0805YD225KAT2A" 0805_HV 22.835,100.965 r0 top
C10 "06035A101JAT2A" 0603 24.638,98.133 r270 top
C11 "0805YD106MAT2A" 0805_HV 22.301,108.483 r180 top
C12 "C2012X5R1E106K125AB" 0805_HV 44.933,118.339 r0 top
C13 "C0603C106M9PACTU" 0603 40.919,120.802 r270 top
C14 "06031A330JAT2A" 0603 7.422,18.826 r180 top
C15 "06031A330JAT2A" 0603 7.422,20.401 r180 top
C16 "06031C103JAT2A" 0603 40.284,32.41 r90 top
C17 "C0603C105K4PACTU" 0603 38.735,32.41 r90 top
C18 "0603YC104JAT2A" 0603 51.372,27.28 r0 top
C19 "0603YC104JAT2A" 0603 51.372,25.756 r0 top
C20 "C0603C105K4PACTU" 0603 29.147,18.644 r180 top
C21 "0603YC104JAT2A" 0603 29.134,20.142 r180 top
C22 "C0603C225K8PACTU" 0603 51.372,21.209 r0 top
C23 "C0603C105K4PACTU" 0603 51.372,22.733 r0 top
C24 "0603YC104JAT2A" 0603 51.372,24.232 r0 top
C25 "06031C103JAT2A" 0603 41.808,32.41 r90 top
C26 "C0603C223K3RACTU" 0603 29.134,24.638 r180 top
C27 "06031C103JAT2A" 0603 43.307,32.436 r90 top
C28 "06033C104JAT2A" 0603 29.147,17.12 r180 top
C29 "C0603C225K9PACTU" 0603 146.944,28.313 r180 top
C30 "C0603C225K9PACTU" 0603 51.372,19.66 r180 top
C31 "C0603C225K9PACTU" 0603 51.968,9.246 r180 top
C32 "06035A220JAT2A" 0603 157,16.75 r0 top
C33 "06033C101KAT2A" 0603 142,21.25 r180 top
C34 "06035A220JAT2A" 0603 150.25,46.4 r180 top
C35 "06035A220JAT2A" 0603 150.25,78.15 r180 top
C36 "06035A220JAT2A" 0603 150.25,109.9 r180 top
C37 "CKG57NX5R1H226M500JH" CKG57N 32.512,76.53 r270 top
C38 "CKG57NX5R1H226M500JH" CKG57N 26.162,76.53 r270 top
C39 "GRM188R71E104KA01D" 0603 22.3,14.1 r270 top
C39 "06031C102JAT2A" 0603 22.2,48.336 r90 top
C40 "CKG57NX5R1H226M500JH" CKG57N 26.162,50.648 r90 top
C41 "CKG57NX5R1H226M500JH" CKG57N 32.588,50.622 r90 top
C42 "C5750X7S2A106M" 2220 79.298,17.85 r270 top
C43 "B37941K9105K62" 0805_HV 175.92,69.494 r270 top
C44 "GRM32ER61C476ME15L" 1210 147.5,2 r180 top
C45 "06031C102JAT2A" 0603 22.225,51.587 r90 top
C46 "B37941K9105K62" 0805_HV 175.92,65.557 r270 top
C47 "EMVE101GTR331MMN0S" CAPSMT_62_MN0 12.395,63.602 r270 top
C48 "EMVA250ADA471MJA0G" CAPSMT_62_JA0 183.82,62.941 r270 top
C49 "CKG57NX5R1H226M500JH" CKG57N 32.512,67.64 r270 top
C50 "CKG57NX5R1H226M500JH" CKG57N 26.162,67.64 r270 top
C51 "06031C102JAT2A" 0603 20.168,51.587 r270 top
C52 "CKG57NX5R1H226M500JH" CKG57N 26.162,59.131 r90 top
C53 "CKG57NX5R1H226M500JH" CKG57N 32.512,59.131 r90 top
C54 "C5750X7S2A106M" 2220 73.298,17.85 r270 top
C55 "B37941K9105K62" 0805_HV 175.895,61.443 r270 top
C56 "GRM32ER61C476ME15L" 1210 147,13.25 r180 top
C57 "06031C102JAT2A" 0603 20.193,48.336 r270 top
C58 "B37941K9105K62" 0805_HV 175.895,57.506 r270 top
C59 "06035A331JAT2A" 0603 29.134,21.615 r180 top
C60 "06033C104KAT2A" 0603 80,7.212 r90 top
C61 "0805YD225KAT2A" 0805_HV 77,2.85 r180 top
C62 "C2012X5R1E475K125AB" 0805_HV 24.1,14.1 r270 top
C63 "06031C103JAT2A" 0603 58.153,35.319 r0 top
C64 "C5750X7S2A106M" 2220 79.298,49.5 r270 top
C65 "GRM32ER61C476ME15L" 1210 147.25,93.5 r180 top
C66 "C5750X7S2A106M" 2220 73.298,49.5 r270 top
C67 "GRM32ER61C476ME15L" 1210 147.25,82.45 r180 top
C68 "06035A331JAT2A" 0603 29.147,23.114 r180 top
C69 "06033C104KAT2A" 0603 80,38.862 r90 top
C70 "0805YD225KAT2A" 0805_HV 77,34.5 r180 top
C71 "C0603C225K8PACTU" 0603 32.7,32.4 r90 top
C72 "06031C103JAT2A" 0603 58.166,26.149 r0 top
C73 "C5750X7S2A106M" 2220 73.298,81.25 r270 top
C74 "GRM32ER61C476ME15L" 1210 147.25,61.75 r180 top
C75 "C5750X7S2A106M" 2220 79.298,81.25 r270 top
C76 "GRM32ER61C476ME15L" 1210 147.25,50.7 r180 top
C77 "06035A331JAT2A" 0603 29.147,26.162 r180 top
C78 "06033C104KAT2A" 0603 80,70.612 r90 top
C79 "0805YD225KAT2A" 0805_HV 77,66.25 r180 top
C80 "C0603C225K8PACTU" 0603 29.147,27.635 r180 top
C81 "06031C103JAT2A" 0603 58.166,29.197 r0 top
C82 "C5750X7S2A106M" 2220 73.298,113 r270 top
C83 "GRM32ER61C476ME15L" 1210 147.25,114.2 r180 top
C84 "C5750X7S2A106M" 2220 79.298,113 r270 top
C85 "GRM32ER61C476ME15L" 1210 147.25,125.25 r180 top
C86 "06035A331JAT2A" 0603 29.147,29.108 r180 top
C87 "06033C104KAT2A" 0603 80,102.362 r90 top
C88 "0805YD225KAT2A" 0805_HV 77,98 r180 top
C89 "C0603C225K8PACTU" 0603 29.147,30.658 r180 top
C90 "0603YC104JAT2A" 0603 58.166,32.271 r0 top
C91 "06033C104JAT2A" 0603 152,22.5 r270 top
C93 "06033C104JAT2A" 0603 151,69.25 r0 top
C94 "C0603C225K8PACTU" 0603 34.2,32.4 r90 top
C95 "06033C104JAT2A" 0603 151.25,37.5 r0 top
C97 "06033C104JAT2A" 0603 151,101 r0 top
C99 "0805YD225KAT2A" 0805_HV 137.75,28 r0 top
C100 "0805YD225KAT2A" 0805_HV 138.5,21.25 r0 top
C101 "0805YD225KAT2A" 0805_HV 151,28.5 r180 top
C102 "0805YD225KAT2A" 0805_HV 149.75,25.5 r90 top
C103 "C0603C223K3RACTU" 0603 37.211,32.41 r90 top
C104 "06035A220JAT2A" 0603 157.75,26.75 r90 top
C105 "06031C331JAT2A" 0603 142,28 r180 top
C106 "C0603C105K3RACTU" 0603_095 144.25,19.75 r0 top
C107 "C0603X102K5RACTU" 0603 138,18.5 r180 top
C108 "C0603C105K3RACTU" 0603_095 155.75,76.75 r180 top
C109 "C0603C105K3RACTU" 0603_095 155.75,45 r180 top
C110 "C0603X102K5RACTU" 0603 146.588,69 r0 top
C111 "C0603X102K5RACTU" 0603 146.588,37.25 r0 top
C112 "C0603C105K3RACTU" 0603_095 155.75,108.5 r180 top
C113 "C0603X102K5RACTU" 0603 146.588,100.75 r0 top
C114 "C0603C101J5GAC" 0603 47.5,109.5 r90 top
C115 "06031C103JAT2A" 0603 35.7,32.4 r90 top
C116 "GRM32ER61C476ME15L" 1210 160.25,108.25 r180 top
C117 "GRM32ER61C476ME15L" 1210 160.25,111.5 r180 top
C118 "GRM32ER61C476ME15L" 1210 160,76.5 r180 top
C119 "GRM32ER61C476ME15L" 1210 160,79.75 r180 top
C120 "GRM32ER61C476ME15L" 1210 160,48 r180 top
C121 "GRM32ER61C476ME15L" 1210 160,44.75 r180 top
C122 "GRM32ER61C476ME15L" 1210 174.25,19.75 r0 top
C123 "GRM32ER61C476ME15L" 1210 174.25,23.25 r0 top
D1 "BAS21-7-F" SOT-23#1 42.52,108.42 r0 top
D2 "LTST-C170KRKT" LED_LTST-C170 62.75,7.5 r0 top
D3 "BAS21-7-F" SOT-23#1 18.669,97.485 r180 top
D4 "BAS21-7-F" SOT-23#1 42.494,101.841 r0 top
D5 "MBR0540T1G" SOD-123 40.97,114.173 r270 top
D6 "MBR0540T1G" SOD-123 46.279,114.325 r90 top
D7 "LTST-C170KRKT" LED_LTST-C170 30.886,117.45 r270 top
D8 "MMSZ4699-V" SOD-123 141.75,13.75 r270 top
D9 "MMSZ4699-V" SOD-123 134.1,18.9 r90 top
D10 "MMSZ4699-V" SOD-123 146,44.75 r90 top
D11 "MMSZ4699-V" SOD-123 135.75,62.25 r0 top
D12 "MMSZ4699-V" SOD-123 146,76.5 r90 top
D13 "UPS115UE3/TR7" DO-216AA 84.836,19.658 r180 top
D14 "MMSZ4699-V" SOD-123 146,108.25 r90 top
D15 "MMSZ4699-V" SOD-123 135.75,125.5 r0 top
D16 "LTST-C170KRKT" LED_LTST-C170 62.75,5.25 r0 top
D17 "MBR0540T1G" SOD-123 49.7,112.3 r90 top
D18 "MMSZ4699-V" SOD-123 135.8,94.2 r0 top
D19 "UPS115UE3/TR7" DO-216AA 83.25,12.1 r180 top
D20 "UPS115UE3/TR7" DO-216AA 84.836,51.308 r180 top
D21 "UPS115UE3/TR7" DO-216AA 83.25,43.75 r180 top
D22 "UPS115UE3/TR7" DO-216AA 84.836,83.058 r180 top
D23 "UPS115UE3/TR7" DO-216AA 83.25,75.5 r180 top
D24 "UPS115UE3/TR7" DO-216AA 84.836,114.808 r180 top
D25 "UPS115UE3/TR7" DO-216AA 83.25,107.25 r180 top
FID1 "Fiducial" Fiducial10-20 19.9,1.7 r0 top
FID2 "Fiducial" Fiducial10-20 22.8,125 r0 top
FID3 "Fiducial" Fiducial10-20 178.5,10.8 r0 top
H1 "NY PMS 440 0025 PH" "NY PMS 440 0025 PH" 65.75,110 r90 top
H2 "NY PMS 440 0025 PH" "NY PMS 440 0025 PH" 65.75,78.5 r90 top
H3 "NY PMS 440 0025 PH" "NY PMS 440 0025 PH" 65.75,48.5 r90 top
H4 "NY PMS 440 0025 PH" "NY PMS 440 0025 PH" 65.75,15 r90 top
H5 "NY PMS 440 0025 PH" "NY PMS 440 0025 PH" 157.25,35.687 r90 top
H6 "NY PMS 440 0025 PH" "NY PMS 440 0025 PH" 157.25,99.25 r90 top
H7 "NY PMS 440 0025 PH" "NY PMS 440 0025 PH" 157.25,67.5 r90 top
J1 "5103308-1" CONN_5103308-1 11.3,26.2 r0 top
J2 "90562" Morris_90562 188.722,93.98 r180 top
J3 "90562" Morris_90562 1.778,86.36 r0 top
J4 "90562" Morris_90562 188.722,78.74 r180 top
J5 "90562" Morris_90562 1.778,40.64 r0 top
J6 "90562" Morris_90562 188.722,33.02 r180 top locked
J7 "90562" Morris_90562 188.722,48.26 r180 top locked
J8 "22-27-2021" MOLEX_22-27-2021 53.086,123.19 r180 top locked
J9 "22-27-2021" MOLEX_22-27-2021 53.086,3.81 r0 top locked
J10 "800-10-002-10-001000" Mill-Max_800-10-002-10-001000 29.896,12.827 r0 top
J11 "22-27-2021" MOLEX_22-27-2021 17,118 r270 top
J12 "TSW-104-07-G-S" TSW-104-07-G-S 13.1,9.7 r315 top
L1 "XAL1580-102MEB" XAL1580 44.653,71.755 r270 top
L2 "XAL1580-102MEB" XAL1580 44.653,55.245 r270 top
L3 "SER2814H-222KL" IND_SER2814 116.141,17 r0 top
L4 "SER2814H-222KL" IND_SER2814 116.163,49.147 r0 top
L5 "SER2814H-222KL" IND_SER2814 116.163,80.897 r0 top
L6 "SER2814H-222KL" IND_SER2814 116.163,112.647 r0 top
LBL1 "Size: 0.65\" x 0.20 \"" Label_650x200 164.3,4.4 r0 top
Logo1 "Texas Instruments" TI_Stacked_Overlay_Small 40.5,89.1 r0 top
Logo2 "Pb-Free Symbol" Pb-Free_Overlay_Small 158.1,9.5 r0 top
Logo3 "FCC disclaimer" FCC_disclaimer 35.1,92.8 r0 top
Logo4 "DANGER HIGH VOLTAGE" IEC_HighVoltage_Small 19.5,83 r0 top
Logo5 "DANGER HIGH VOLTAGE" IEC_HighVoltage_Small 59.6,100.5 r0 top
Logo6 "CAUTION HOT SURFACE" IEC_HotSurface_Small 163.2,11.7 r0 top
NT1 "Net-Tie" Net-Tie_10mil 21.2,41.8 r90 top net-tie
Q1 "FDN302P" SOT-23#1 43.561,115.164 r90 top
Q2 "2N7002E-T1-E3" SOT-23#1 6.02,105.258 r270 top
Q3 "2N7002E-T1-E3" SOT-23#1 49.987,103.784 r90 top
Q4 "CSD17570Q5B" TRANS_NexFET_Q5B#1 136.5,3.5 r180 top
Q5 "IPB180N08S402ATMA1" DDPAK-7 93.218,24.892 r0 top
Q6 "IPB180N08S402ATMA1" DDPAK-7 92.456,6.096 r270 top
Q7 "CSD17570Q5B" TRANS_NexFET_Q5B#1 135.844,42.765 r270 top
Q8 "CSD17570Q5B" TRANS_NexFET_Q5B#1 136.5,9.5 r180 top
Q9 "CSD17570Q5B" TRANS_NexFET_Q5B#1 135.844,106.265 r270 top
Q11 "2N7002E-T1-E3" SOT-23#1 48.956,32.423 r180 top
Q12 "2N7002E-T1-E3" SOT-23#2 138.25,15.75 r270 top
Q14 "2N7002E-T1-E3" SOT-23#1 44.272,37.516 r180 top
Q15 "ZXMP10A13FTA" SOT-23#2 134.75,14.25 r270 top
Q16 "ECH8102-TL-H" ECH8 86.25,16.35 r270 top
Q17 "ECH8102-TL-H" ECH8 79,11.35 r180 top
Q18 "IPB180N08S402ATMA1" DDPAK-7 93.218,56.9 r0 top
Q20 "CSD17570Q5B" TRANS_NexFET_Q5B#2 141.991,42.765 r270 top
Q22 "IPB180N08S402ATMA1" DDPAK-7 92.456,37.75 r270 top
Q23 "2N7002E-T1-E3" SOT-23#2 146.588,40 r90 top
Q24 "ECH8102-TL-H" ECH8 86.25,48 r270 top
Q25 "ZXMP10A13FTA" SOT-23#2 135,59.25 r270 top
Q26 "CSD17570Q5B" TRANS_NexFET_Q5B#2 135.844,74.515 r270 top
Q27 "ECH8102-TL-H" ECH8 79,43 r180 top
Q28 "IPB180N08S402ATMA1" DDPAK-7 93.218,88.65 r0 top
Q30 "CSD17570Q5B" TRANS_NexFET_Q5B#2 141.991,74.515 r270 top
Q32 "IPB180N08S402ATMA1" DDPAK-7 92.456,69.5 r270 top
Q34 "2N7002E-T1-E3" SOT-23#2 146.588,71.75 r90 top
Q35 "ZXMP10A13FTA" SOT-23#2 135,91 r270 top
Q36 "ECH8102-TL-H" ECH8 86.25,79.75 r270 top
Q37 "ECH8102-TL-H" ECH8 79,74.75 r180 top
Q38 "IPB180N08S402ATMA1" DDPAK-7 93.218,120.4 r0 top
Q39 "CSD17570Q5B" TRANS_NexFET_Q5B#2 141.991,106.265 r270 top
Q42 "IPB180N08S402ATMA1" DDPAK-7 92.456,101.25 r270 top
Q43 "2N7002E-T1-E3" SOT-23#2 146.588,103.5 r90 top
Q45 "ZXMP10A13FTA" SOT-23#2 135,122.5 r270 top
Q46 "ECH8102-TL-H" ECH8 86.25,111.5 r270 top
Q47 "ECH8102-TL-H" ECH8 79,106.5 r180 top
R1 "RC0603FR-07330RL" 0603 59,7.5 r180 top
R2 "RC0603FR-0739KL" 0603 22.504,104.521 r180 top
R3 "CRCW0603150KFKEA" 0603 8.661,103.683 r90 top
R4 "RC0603FR-07120KL" 0603 10.617,100.533 r270 top
R5 "CRCW060349R9FKEA" 0603 41.529,105.143 r90 top
R6 "RC0603FR-0727KL" 0603 21.641,98.158 r270 top
R7 "CRCW060310K0FKEA" 0603 8.661,100.508 r90 top
R8 "CRCW06031K00JNEA" 0603 43.586,112.471 r0 top
R9 "CRCW06031K00JNEA" 0603 30.937,120.777 r90 top
R10 "RC0603FR-07560RL" 0603 47.473,103.289 r90 top
R11 "CRCW06033K00JNEA" 0603 23.114,98.133 r90 top
R12 "CRCW0603100KJNEA" 0603 49.809,101.016 r180 top
R13 "RG1608P-152-B-T5" 0603 10.623,18.826 r0 top
R14 "RG1608P-152-B-T5" 0603 10.648,20.426 r0 top
R15 "MCR03EZPJ000" 0603 51.384,28.778 r180 top
R16 "RC0603FR-07330RL" 0603 59,5.75 r180 top
R17 "CRCW06031K00FKEA" 0603 54.75,16.694 r0 top
R19 "CRCW06031K00JNEA" 0603 29.25,15.5 r0 top
R20 "MCR03EZPJ000" 0603 80,4.088 r270 top
R21 "MCR03EZPJ000" 0603 80,35.738 r270 top
R22 "MCR03EZPJ000" 0603 80,67.488 r270 top
R23 "MCR03EZPJ000" 0603 80,99.238 r270 top
R24 "CRCW0603100RFKEA" 0603 3.231,19.562 r270 top
R26 "CRCW0603100RFKEA" 0603 4.781,19.562 r270 top
R27 "ERJ-M1WTF2M0U" 2512 145.5,5.5 r0 top
R28 "CRCW06031K10FKEA" 0603 39.75,37.5 r90 top
R29 "CRCW06031K00FKEA" 0603 44.856,32.423 r90 top
R30 "RG1608P-103-B-T5" 0603 83.75,16.35 r270 top
R33 "RC0603FR-0736KL" 0603 41.783,37.516 r270 top
R34 "CRCW06031K00JNEA" 0603 138.25,13 r0 top
R35 "CRCW06038K06FKEA" 0603 46.406,32.423 r270 top
R36 "ERJ-M1WTF2M0U" 2512 145.5,9.5 r0 top
R38 "CRCW06031K00JNEA" 0603 47.066,37.516 r270 top
R39 "RG1608P-103-B-T5" 0603 76.25,10.85 r90 top
R40 "CRCW06031K00JNEA" 0603 51.537,32.36 r270 top
R41 "CRCW06031K00JNEA" 0603 134.25,24 r90 top
R42 "CRCW06031K00JNEA" 0603 24.181,20.803 r0 top
R43 "CRCW06031K00JNEA" 0603 153.75,15.25 r0 top
R43 "CRCW08050000Z0EA" 0805_HV 12.6,15.8 r0 top
R44 "CRCW060326K1FKEA" 0603 153.75,17 r180 top
R45 "CRCW06031K00JNEA" 0603 24.181,32.791 r0 top
R46 "CRCW06031K00JNEA" 0603 157,15.25 r180 top
R47 "CRCW060326K1FKEA" 0603 55.702,36.258 r270 top
R48 "CRCW060340K2FKEA" 0603 58.153,36.893 r180 top
R49 "CRCW060326K1FKEA" 0603 147.5,16.75 r0 top
R51 "CRCW06031K65FKEA" 0603 147.5,18.25 r180 top
R52 "ERJ-M1WTF2M0U" 2512 145.75,54.25 r0 top
R53 "RG1608P-103-B-T5" 0603 83.75,48 r270 top
R56 "CRCW06031K00JNEA" 0603 134,48.25 r270 top
R57 "ERJ-M1WTF2M0U" 2512 145.75,58.25 r0 top
R59 "RG1608P-103-B-T5" 0603 76.25,42.5 r90 top
R60 "CRCW06031K00JNEA" 0603 24.181,22.327 r0 top
R61 "CRCW06031K00JNEA" 0603 150.25,48.35 r0 top
R62 "CRCW060326K1FKEA" 0603 153,47.25 r270 top
R63 "CRCW06031K00JNEA" 0603 139.75,62.75 r0 top
R64 "CRCW06031K00JNEA" 0603 24.181,31.293 r0 top
R65 "CRCW06031K00JNEA" 0603 148,47.2 r270 top
R66 "CRCW060326K1FKEA" 0603 55.753,26.759 r90 top
R67 "CRCW060340K2FKEA" 0603 58.166,27.673 r180 top
R68 "CRCW060326K1FKEA" 0603 148,43.5 r90 top
R70 "CRCW06031K65FKEA" 0603 150.75,34.75 r90 top
R71 "ERJ-M1WTF2M0U" 2512 145.75,86 r0 top
R72 "RG1608P-103-B-T5" 0603 83.75,79.75 r270 top
R75 "CRCW06031K00JNEA" 0603 134,80 r270 top
R76 "ERJ-M1WTF2M0U" 2512 145.75,90 r0 top
R78 "RG1608P-103-B-T5" 0603 76.25,74.25 r90 top
R79 "CRCW06031K00JNEA" 0603 24.181,25.298 r0 top
R80 "CRCW06031K00JNEA" 0603 150.25,80.1 r0 top
R81 "CRCW060326K1FKEA" 0603 153,79 r270 top
R82 "CRCW06031K00JNEA" 0603 139.75,94.5 r0 top
R83 "CRCW06031K00JNEA" 0603 24.181,26.797 r0 top
R84 "CRCW06031K00JNEA" 0603 148,78.95 r270 top
R85 "CRCW060326K1FKEA" 0603 55.753,29.972 r90 top
R86 "CRCW060340K2FKEA" 0603 58.154,30.721 r180 top
R87 "CRCW060326K1FKEA" 0603 148,75.25 r90 top
R89 "CRCW06031K65FKEA" 0603 150.75,66.5 r90 top
R90 "ERJ-M1WTF2M0U" 2512 145.75,117.75 r0 top
R91 "RG1608P-103-B-T5" 0603 83.75,111.5 r270 top
R94 "CRCW06031K00JNEA" 0603 134,111.75 r270 top
R95 "ERJ-M1WTF2M0U" 2512 145.75,121.75 r0 top
R97 "RG1608P-103-B-T5" 0603 76.25,106 r90 top
R98 "CRCW06031K00JNEA" 0603 24.181,28.27 r0 top
R99 "CRCW06031K00JNEA" 0603 150.25,111.85 r0 top
R100 "CRCW060326K1FKEA" 0603 153,110.75 r270 top
R101 "CRCW06031K00JNEA" 0603 139.75,125.75 r0 top
R102 "CRCW06031K00JNEA" 0603 24.181,29.769 r0 top
R103 "CRCW06031K00JNEA" 0603 148,110.7 r270 top
R104 "CRCW060326K1FKEA" 0603 55.753,33.16 r270 top
R105 "CRCW060340K2FKEA" 0603 58.153,33.82 r180 top
R106 "CRCW060326K1FKEA" 0603 148,107 r90 top
R108 "CRCW06031K65FKEA" 0603 150.75,98.25 r90 top
R109 "CRCW06032K00FKEA" 0603 136,25.25 r90 top
R110 "CRCW06032K00FKEA" 0603 137.75,25.25 r270 top
R111 "CRCW06031K00FKEA" 0603 138.75,23 r0 top
R112 "CRCW0603100KJNEA" 0603 139.5,25.25 r270 top
R113 "CRCW06032K00FKEA" 0603 153.75,30 r270 top
R114 "CRCW06032K00FKEA" 0603 151.5,25.75 r270 top
R115 "CRCW06031K00FKEA" 0603 145.25,21.25 r0 top
R116 "CRCW0603100KJNEA" 0603 148,24 r270 top
R117 "CRCW06031K00FKEA" 0603 24.181,23.825 r0 top
R118 "CRCW060310K0FKEA" 0603 33.452,12.979 r270 top
R119 "CRCW06031K00FKEA" 0603 36.75,37.5 r270 top
R120 "ERJ-3GEY0R00V" 0603 151.25,18.5 r180 top
R121 "CRCW060331K6FKEA" 0603 155.5,26 r180 top
R122 "CRCW060349R9FKEA" 0603 45.25,110.25 r0 top
R124 "CRCW06031K00JNEA" 0603l 138.25,19.75 r180 top
R125 "CRCW06031K00JNEA" 0603 145.75,34 r270 top
R126 "CRCW06031K00JNEA" 0603 145.75,66.25 r270 top
R127 "CRCW06031K00JNEA" 0603 145.75,97.5 r270 top
R128 "CRCW060375R0FKEA" 0603 140.25,29.75 r0 top
R130 "CRCW060310R0FKEA" 0603 143.5,30.75 r180 top
R135 "CRCW08050000Z0EA" 0805_HV 17.9,10.3 r0 top
S1 "SKRKAEE010" SW_SKRKAEE010 7.7,16.2 r0 top
T1 "BSEPC10-138" XFMR_12X12.5-8P 32.766,103.734 r180 top
TP1 "5002" Keystone5002 26.619,116.357 r90 top
TP2 "5002" Keystone5002 26.187,82.931 r0 top
TP3 "5016" Testpoint_Keystone_Compact 83.5,26.75 r90 top
TP4 "5002" Keystone5002 103.5,3.5 r0 top
TP5 "5002" Keystone5002 182.651,104.521 r0 top
TP6 "5002" Keystone5002 37.897,40.818 r0 top
TP7 "5002" Keystone5002 44.348,40.818 r0 top
TP8 "5002" Keystone5002 50.851,40.818 r90 top
TP9 "5002" Keystone5002 70.25,9.85 r90 top
TP10 "5002" Keystone5002 141.25,18.75 r90 top
TP11 "5002" Keystone5002 36.5,125 r180 top
TP13 "5002" Keystone5002 22.809,3.404 r90 top
TP14 "5002" Keystone5002 73.5,11.35 r90 top
TP15 "5002" Keystone5002 37.719,3.378 r90 top
TP16 "5002" Keystone5002 22.86,7.798 r90 top
TP17 "5002" Keystone5002 59,2.25 r90 top
TP18 "5002" Keystone5002 47.6,40.818 r90 top
TP19 "5002" Keystone5002 37.668,7.747 r90 top
TP20 "5002" Keystone5002 148.25,20.75 r90 top
TP21 "5002" Keystone5002 70.25,41.5 r0 top
TP22 "5002" Keystone5002 103.5,35.5 r90 top
TP23 "5002" Keystone5002 73,2.1 r90 top
TP24 "5002" Keystone5002 156,29.5 r90 top
TP25 "5002" Keystone5002 148.25,34.5 r90 top
TP26 "5002" Keystone5002 33.909,7.874 r90 top
TP27 "5002" Keystone5002 73.5,43 r90 top
TP28 "5002" Keystone5002 41.275,3.353 r90 top
TP29 "5002" Keystone5002 26.518,3.378 r90 top
TP31 "5002" Keystone5002 73,33.75 r90 top
TP32 "5002" Keystone5002 41.25,7.772 r90 top
TP33 "5002" Keystone5002 156,42.75 r270 top
TP35 "5002" Keystone5002 103.5,67.75 r90 top
TP36 "5002" Keystone5002 143,62 r90 top
TP37 "5002" Keystone5002 70.25,73.25 r90 top
TP38 "5002" Keystone5002 148.25,66.5 r90 top
TP39 "5002" Keystone5002 33.909,3.404 r90 top
TP40 "5002" Keystone5002 73.5,74.75 r90 top
TP41 "5002" Keystone5002 44.831,3.277 r0 top
TP42 "5002" Keystone5002 30.251,7.798 r90 top
TP43 "5002" Keystone5002 73,65.5 r90 top
TP44 "5002" Keystone5002 143,93.75 r90 top
TP45 "5002" Keystone5002 44.831,7.772 r90 top
TP46 "5002" Keystone5002 156,74.5 r270 top
TP47 "5002" Keystone5002 70.25,105 r0 top
TP48 "5002" Keystone5002 103.5,98.75 r90 top
TP49 "5002" Keystone5002 148.25,98 r90 top
TP50 "5002" Keystone5002 30.251,3.404 r90 top
TP51 "5002" Keystone5002 73.5,106.5 r90 top
TP52 "5002" Keystone5002 48.438,3.277 r90 top
TP53 "5002" Keystone5002 26.518,7.823 r90 top
TP55 "5002" Keystone5002 73,97.25 r90 top
TP56 "5002" Keystone5002 48.412,7.798 r90 top
TP57 "5002" Keystone5002 156,106.25 r270 top
TP58 "5002" Keystone5002 143,125.5 r90 top
TP59 "5002" Keystone5002 15.2,18.4 r90 top
TP60 "5002" Keystone5002 18.4,4.4 r90 top
U1 "LM34927MR" DDA0008B_M 16.002,101.549 r0 top
U2 "TLV1117-33IDCY" DCY0003A_N 36.398,118.72 r90 top
U3 "UCD3138128PFC" PFC0080A_N 40.31,21.438 r0 top
U4 "UCC2721XDRM" DRM0008A 75.692,6.392 r180 top
U5 "OPA2211AIDDA" DDA0008C_N 155.5,21.5 r90 top
U6 "UCC2721XDRM" DRM0008A 75.692,38.042 r180 top
U7 "OPA211AID" D0008A_N 151.5,41.975 r270 top
U8 "UCC2721XDRM" DRM0008A 75.692,69.792 r180 top
U9 "OPA211AID" D0008A_N 151.5,73.725 r270 top
U10 "UCC2721XDRM" DRM0008A 75.692,101.542 r180 top
U11 "OPA211AID" D0008A_N 151.5,105.475 r270 top
U12 "TLV3202AID" D0008A_l 143.75,24.75 r0 top
U13 "SN74AHC1G08DBV" DBV0005A_N 52.375,11.506 r180 top
U14 "SN74LVC2G34DRL" DRL0006A_N 49.759,14.58 r0 top
U15 "REF1112AIDBZT" DBZ0003A_N 144.25,17 r270 top
U16 "REF1112AIDBZT" DBZ0003A_N 155.5,79.5 r90 top
U17 "REF1112AIDBZT" DBZ0003A_N 155.5,47.75 r90 top
U18 "REF1112AIDBZT" DBZ0003A_N 155.5,111.25 r90 top
U19 "SN65HVD233D" D0008A_L 18,14.1 r180 top
XF1 "3587" KEYSTONE_3587 70.3,26.6 r0 top
XF3 "3587" KEYSTONE_3587 69,58 r0 top
XF5 "3587" KEYSTONE_3587 69,89.75 r0 top
XF7 "3587" KEYSTONE_3587 69,121.5 r0 top
ZZ1 "This Assembly Note is for PCB labels only" AssemblyNoteLabel 29.7,135.1 r0 top
ZZ2 "These assemblies are ESD sensitive, ESD precautions shall be observed." AssemblyNote 30.216,139.927 r0 top
ZZ3 "These assemblies must be clean and free from flux and all contaminants. Use of no clean flux is not acceptable." AssemblyNote 30.216,144.423 r0 top
ZZ4 "These assemblies must comply with workmanship standards IPC-A-610 Class 2, unless otherwise specified." AssemblyNote 30.216,148.944 r0 top

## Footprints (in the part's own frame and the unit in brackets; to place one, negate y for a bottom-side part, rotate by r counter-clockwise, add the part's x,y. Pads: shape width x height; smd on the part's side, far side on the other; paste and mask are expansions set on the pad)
0603 [mm] "0603 from SM-752 data"
  rect 1x0.95 smd: 1(-0.8,0) 2(0.8,0)
  silkscreen extent -1.52,-0.69 1.52,0.69, body extent -0.87,-0.47 0.87,0.47, height 0.85
0603_095 [mm] "0603_095"
  rect 1x1 smd: 1(-0.8,0) 2(0.8,0)
  silkscreen extent -0.1,-0.58 0.1,0.58, body extent -0.87,-0.48 0.87,0.48, height 0.95
0603l [mm] "0603 from SM-752 data"
  rect 0.8x0.85 smd: 1(-0.7,0) 2(0.7,0)
  silkscreen extent -0.07,-0.33 0.07,0.33, body extent -0.87,-0.47 0.87,0.47, height 0.85
0805_HV [mil] "0805 with 30mil clearance between pads"
  rect 50x63 smd: 1(-40,0) 2(40,0)
  silkscreen extent -74,-40 74,40, body extent -43,-29 43,29, height 43
1206 [mm] "1206 from SM-752 data"
  rect 1.3x1.85 smd: 1(-1.45,0) 2(1.45,0)
  silkscreen extent -2.4,-1.21 2.4,1.21, body extent -1.7,-0.9 1.7,0.9, height 1.35
1206_190 [mm] "1206_190"
  rect 1.1x1.6 smd: 1(-1.7,0) 2(1.7,0)
  silkscreen extent -0.9,-1 0.9,1, body extent -1.75,-0.95 1.75,0.95, height 1.9
1210 [mm] "1210 from SM-752 data"
  rect 1.3x2.7 smd: 1(-1.45,0) 2(1.45,0)
  silkscreen extent -2.32,-1.57 2.32,1.57, body extent -1.7,-1.35 1.7,1.35, height 1.35
2220 [mm] "Chip Capacitor, Body 5.7x5.0mm, IPC Medium Density"
  rect 1.6x5.3 smd: 1(-2.6,0) 2(2.6,0)
  silkscreen extent -3.69,-2.94 3.69,2.94, body extent -2.95,-2.62 2.95,2.62, height 1.35
2512 [mm] "Chip Resistor, Body 6.3x3.2mm, IPC Medium Density"
  rect 1.3x3.4 smd: 1(-2.95,0) 2(2.95,0)
  silkscreen extent -1.9,-1.6 1.9,1.6, body extent -3.22,-1.67 3.22,1.67, height 0.71
AssemblyNote [mm] "Assembly Note"
AssemblyNoteLabel [mm] "Assembly Note for PCB Labels"
CAPSMT_62_JA0 [mm] "10 x 10mm:  Chemi-Con JA0"
  rect 4.4x2.2 smd: 1(-4.45,0) 2(4.45,0)
  silkscreen extent -5.25,-5.25 5.25,5.25, body extent -5.26,-5.26 5.26,5.26, height 10.5
CAPSMT_62_MN0 [mm] "18 x 21.5mm:  Chemi-Con MN0"
  rect 8.8x9.6 smd: 1(-6.75,0) 2(6.75,0)
  silkscreen extent -9.6,-9.6 9.6,9.6, body extent -9.6,-9.6 9.6,9.6, height 22
CKG57N [mm] "Chip Capacitor, Body 6.0x5.0x5.0mm,"
  rect 2x5 smd: 1(-2.95,0) 2(2.95,0)
  silkscreen extent -3.2,-2.8 3.2,2.8, body extent -3.3,-2.75 3.3,2.75, height 5.5
CONN_5103308-1 [mm] "TE Connectivity (AMP) Rev E datasheet"
  rect 1.65x1.65 hole 1.016 mask+0: 1(-5.08,-1.27)
  round 1.65 hole 1.016 mask+0: 2(-5.08,1.27) 3(-2.54,-1.27) 4(-2.54,1.27) 5(0,-1.27) 6(0,1.27) 7(2.54,-1.27) 8(2.54,1.27) 9(5.08,-1.27) 10(5.08,1.27)
  silkscreen extent -10.16,-4.57 10.16,4.57, body extent -10.16,-4.57 10.16,4.57, height 9.87
D0008A_l [mm] "SOIC, 8-Leads, Body 4.9x3.9mm, Pitch 1.27mm, IPC High Density"
  oval 1.25x0.55 smd: 1(-2.625,1.905) 2(-2.625,0.635) 3(-2.625,-0.635) 4(-2.625,-1.905) 5(2.625,-1.905) 6(2.625,-0.635) 7(2.625,0.635) 8(2.625,1.905)
  silkscreen extent -3.1,-2.5 0.9,2.5, body extent -3,-2.45 3,2.45, height 1.63
D0008A_L [mm] "SOIC, 8-Leads, Body 4.9x3.9mm, Pitch 1.27mm, IPC High Density"
  oval 1.25x0.55 smd: 1(-2.625,1.905) 2(-2.625,0.635) 3(-2.625,-0.635) 4(-2.625,-1.905) 5(2.625,-1.905) 6(2.625,-0.635) 7(2.625,0.635) 8(2.625,1.905)
  silkscreen extent -3.1,-2.5 0.9,2.5, body extent -3,-2.45 3,2.45, height 1.63
D0008A_N [mm] "SOIC, 8-Leads, Body 4.9x3.9mm, Pitch 1.27mm, IPC Medium Density"
  oval 1.45x0.6 smd: 1(-2.725,1.905) 2(-2.725,0.635) 3(-2.725,-0.635) 4(-2.725,-1.905) 5(2.725,-1.905) 6(2.725,-0.635) 7(2.725,0.635) 8(2.725,1.905)
  silkscreen extent -3.3,-2.5 0.9,2.5, body extent -3,-2.45 3,2.45, height 1.63
DBV0005A_N [mm] "SOT23, 5-Leads, Body 2.9x1.6mm, Pitch 0.95mm, Lead Span 2.8mm, IPC Medium Density"
  rrect17% 1x0.6 smd: 1(-1.375,0.95) 2(-1.375,0) 3(-1.375,-0.95) 4(1.375,-0.95) 5(1.375,0.95)
  silkscreen extent -1.63,-1.55 0.38,1.55, body extent -1.42,-1.46 1.42,1.46, height 1.09
DBZ0003A_N [mm] "SOT23, 3-Leads, Body 2.9x1.3mm, Pitch 0.95mm, Lead Span 2.4mm, IPC Medium Density"
  rrect17% 1x0.6 smd: 1(-1.2,0.95) 2(-1.2,-0.95) 3(1.2,0)
  silkscreen extent -1.65,-1.5 0.7,1.5, body extent -1.26,-1.46 1.26,1.46, height 0.98
DCY0003A_N [mm] "SOT223/SC73, 4-Leads, Body 6.5x3.5mm, Pitch 2.3mm, Lead Span 7mm, IPC Medium Density"
  rect 2.4x1 smd: 1(-2.9,2.3) 2(-2.9,0) 3(-2.9,-2.3)
  rect 2.4x3.3 smd: 4(2.9,0)
  silkscreen extent -3.02,-3.35 1.4,3.47, body extent -3.5,-3.25 3.5,3.25, height 1.62
DDA0008B_M [mm] "SOIC, 8-Leads, Body 4.9x3.9mm, Pitch 1.27mm, Exposed Pad, IPC Low Density"
  rrect100% 1.65x0.65 smd: 1(-2.825,1.905) 2(-2.825,0.635) 3(-2.825,-0.635) 4(-2.825,-1.905) 5(2.825,-1.905) 6(2.825,-0.635) 7(2.825,0.635) 8(2.825,1.905)
  rrect4% 2.41x3.1 smd: 9(0,0)
  silkscreen extent -3.5,-2.47 1.02,2.5, body extent -2.98,-2.45 2.98,2.45, height 1.55
DDA0008C_N [mm] "SOIC, 8-Leads, Body 4.9x3.9mm, Pitch 1.27mm, Exposed Pad, IPC Medium Density"
  rrect100% 1.45x0.6 smd: 1(-2.725,1.905) 2(-2.725,0.635) 3(-2.725,-0.635) 4(-2.725,-1.905) 5(2.725,-1.905) 6(2.725,-0.635) 7(2.725,0.635) 8(2.725,1.905)
  rrect4% 2.4x3 smd: 9(0,0)
  silkscreen extent -3.27,-2.47 1.12,2.5, body extent -3.01,-2.45 3.01,2.45, height 1.7
DDPAK-7 [mil]
  rect 38x138 smd: 1(-150,-347) 2(-100,-347) 3(-50,-347) 5(50,-347) 6(100,-347) 7(150,-347)
  rect 420x458 smd: 4(0,6)
  silkscreen extent -218,-424 219,244, body extent -210,-386 210,240, height 190
DO-216AA [mm] "ST Microelectronics"
  rect 2.32x1.1 smd: 1(-1.16,0)
  rect 1.38x0.75 smd: 2(1.4,0)
  Top Layer region: -1.82,-1.015 0,-1.015 0,1.015 -1.82,1.015
  silkscreen extent -2.58,-1.1 0.63,1.15, body extent -2,-1 1.85,1, height 1.01
DRL0006A_N [mm] "SOTFL, 6-Flat Leads, Body 1.2x1.6x0.6mm, Pitch 0.5mm, IPC Medium Density"
  rect 0.67x0.3 smd: 1(-0.74,0.5) 2(-0.74,0) 3(-0.74,-0.5) 4(0.74,-0.5) 5(0.74,0) 6(0.74,0.5)
  silkscreen extent -1,-1 0.55,1.05, body extent -0.65,-0.85 0.65,0.85, height 0.6
DRM0008A [mm] "TI"
  oval 0.6x0.3 smd: 1(-1.9,1.2) 2(-1.9,0.4) 3(-1.9,-0.4) 4(-1.9,-1.2) 5(1.9,-1.2) 6(1.9,-0.4) 7(1.9,0.4) 8(1.9,1.2)
  rect 2.45x3.38 smd paste-1.25: 9(0,0)
  silkscreen extent -2.2,-2.2 2.2,2.2, body extent -2.05,-2.05 2.05,2.05, height 1.01
ECH8 [mm] "ON-SEMI"
  rect 0.6x0.4 smd: 1(-1.4,0.975) 2(-1.4,0.325) 3(-1.4,-0.325) 4(-1.4,-0.975) 5(1.4,-0.975) 6(1.4,-0.325) 7(1.4,0.325) 8(1.4,0.975)
  silkscreen extent -1.2,1.43 -0.87,1.5, body extent -1.42,-1.48 1.42,1.48, height 0.95
FCC_disclaimer [mm]
Fiducial10-20 [mm]
  round 1 smd mask+0.5: 1(0,0)
  Top Layer keep-out circle w1.178: c0,0 r0.5
IEC_HighVoltage_Small [mm]
  silkscreen extent -2.72,-2.24 2.72,2.47
IEC_HotSurface_Small [mm]
  silkscreen extent -2.72,-2.36 2.72,2.35
IND_SER2814 [mm] "COILCRAFT"
  rect 5.33x5.59 smd: 1(-5.08,-11.505) 2(5.08,-11.505)
  silkscreen extent -14.1,-9.3 13.8,11.73, body extent -14.1,-13.7 13.8,11.75, height 14.22
Keystone5002 [mil] "For Keystone 500x miniature loop terminals"
  round 80 hole 40: 1(0,0)
  silkscreen extent -58,-58 58,58, body extent -49,-49 49,49, height 182
KEYSTONE_3587 [mm] "KEYSTONE"
  rect 1.57x2.82 smd: 1(-6.73,3.04) 2(-6.73,-3.04) 3(6.73,3.04) 4(6.73,-3.04)
  silkscreen extent -10,-3.5 10,3.5, body extent -9.9,-4.31 9.91,4.33, height 8.04
Label_650x200 [mil] "Thermal Transfer Label"
  round 1 on Mech13: 0(0,0)
  silkscreen extent -325,-100 325,100, body extent -326,-101 326,101, height 1
LED_LTST-C170 [mm] "LITE-ON"
  rect 1.2x1.2 smd: 1(-1.05,0) 2(1.05,0)
  silkscreen extent -1.6,-1.1 3,1.1, body extent -1.05,-0.67 1.05,0.67, height 1.1
Mill-Max_800-10-002-10-001000 [mm] "Mill-Max"
  rect 1.5x1.5 hole 0.85: 1(-1.27,0)
  round 1.5 hole 0.85: 2(1.27,0)
  silkscreen extent -2.54,-1.27 2.54,1.78, body extent -2.54,-1.27 2.54,1.27, height 8.13
MOLEX_22-27-2021 [mm] "MOLEX"
  rect 1.8x1.8 hole 1.2: 1(-1.27,0)
  round 1.8 hole 1.2: 2(1.27,0)
  silkscreen extent -3.1,-3 2.63,2.9, body extent -2.51,-3 2.57,2.8, height 11.72
Morris_90562 [mil] "Morris"
  rect 1100x480 smd: 1(0,0)
  round 350 hole 260: 1(237,0)
  silkscreen extent -560,-251 561,251, body extent -543,-225 533,225, height 444
Net-Tie_10mil [mil] "10mil net tie, no solder mask opening, no solder paste"
  rect 10x10 smd paste-5 mask-5: 1(-10,0) 2(10,0)
  Top Layer region: -6,5 6,5 6,-5 -6,-5
"NY PMS 440 0025 PH" [mm] "4-40 nylon screw and mounting hole"
  round 8 / inner round 4.3 / far side round 4.3 hole 4 unplated: 1(0,0)
  body extent -3.3,-3.3 3.3,3.3, height 2.69
Pb-Free_Overlay_Small [mm]
  silkscreen extent -1.16,-1.17 1.17,1.17
PFC0080A_N [mm] "Thin QFP, 80-Leads, Body 12x12mm, Pitch 0.5mm, IPC Medium Density"
  oval 1.8x0.3 smd: 1(-6.55,4.75) 2(-6.55,4.25) 3(-6.55,3.75) 4(-6.55,3.25) 5(-6.55,2.75) 6(-6.55,2.25) 7(-6.55,1.75) 8(-6.55,1.25) 9(-6.55,0.75) 10(-6.55,0.25) 11(-6.55,-0.25) 12(-6.55,-0.75) 13(-6.55,-1.25) 14(-6.55,-1.75) 15(-6.55,-2.25) 16(-6.55,-2.75) 17(-6.55,-3.25) 18(-6.55,-3.75) 19(-6.55,-4.25) 20(-6.55,-4.75) 41(6.55,-4.75) 42(6.55,-4.25) 43(6.55,-3.75) 44(6.55,-3.25) 45(6.55,-2.75) 46(6.55,-2.25) 47(6.55,-1.75) 48(6.55,-1.25) 49(6.55,-0.75) 50(6.55,-0.25) 51(6.55,0.25) 52(6.55,0.75) 53(6.55,1.25) 54(6.55,1.75) 55(6.55,2.25) 56(6.55,2.75) 57(6.55,3.25) 58(6.55,3.75) 59(6.55,4.25) 60(6.55,4.75)
  oval 0.3x1.8 smd: 21(-4.75,-6.55) 22(-4.25,-6.55) 23(-3.75,-6.55) 24(-3.25,-6.55) 25(-2.75,-6.55) 26(-2.25,-6.55) 27(-1.75,-6.55) 28(-1.25,-6.55) 29(-0.75,-6.55) 30(-0.25,-6.55) 31(0.25,-6.55) 32(0.75,-6.55) 33(1.25,-6.55) 34(1.75,-6.55) 35(2.25,-6.55) 36(2.75,-6.55) 37(3.25,-6.55) 38(3.75,-6.55) 39(4.25,-6.55) 40(4.75,-6.55) 61(4.75,6.55) 62(4.25,6.55) 63(3.75,6.55) 64(3.25,6.55) 65(2.75,6.55) 66(2.25,6.55) 67(1.75,6.55) 68(1.25,6.55) 69(0.75,6.55) 70(0.25,6.55) 71(-0.25,6.55) 72(-0.75,6.55) 73(-1.25,6.55) 74(-1.75,6.55) 75(-2.25,6.55) 76(-2.75,6.55) 77(-3.25,6.55) 78(-3.75,6.55) 79(-4.25,6.55) 80(-4.75,6.55)
  silkscreen extent -6.67,-5.25 5.25,5.57, body extent -6,-6 6,6, height 1.2
SOD-123 [mm] "On Semi recommended land pattern"
  rect 0.915x1.22 smd: 1(-1.637,0) 2(1.637,0)
  silkscreen extent -2.74,-1.17 2.03,1.17, body extent -1.93,-0.9 1.93,0.9, height 1.35
SOT-23#1 [mm] "SOT23, 3-Leads, Body 2.9x1.3mm, Pitch 0.95mm, Lead Span 2.5mm, IPC Medium Density"
  rect 1.5x0.6 smd: 1(-0.95,0.95) 2(-0.95,-0.95) 3(0.95,0)
  silkscreen extent 0.2,-1.5 0.7,1.5, body extent -1.16,-1.45 1.21,1.45, height 1
SOT-23#2 [mm] "SOT23, 3-Leads, Body 2.9x1.3mm, Pitch 0.95mm, Lead Span 2.5mm, IPC Medium Density"
  rrect50% 1x0.6 smd: 1(-1.2,0.95) 2(-1.2,-0.95) 3(1.2,0)
  silkscreen extent -1.62,-1.5 0.7,1.5, body extent -1.16,-1.45 1.21,1.45, height 1
SW_SKRKAEE010 [mm] "Alps recommended land pattern"
  rect 0.8x2 smd: 1(-2.1,0) 2(2.1,0)
  silkscreen extent -1.9,-1.44 1.92,1.44, body extent -2.4,-1.45 2.4,1.45, height 1.96
Testpoint_Keystone_Compact [mil] "Compact SMT test point"
  rect 185x135 smd: 1(0,0)
  silkscreen extent -110,-80 110,80, body extent -75,-56 75,56, height 91
TI_Stacked_Overlay_Small [mm]
  silkscreen extent -10.63,-2.49 10.63,2.49
TRANS_NexFET_Q5B#1 [mm] "TI recommended land pattern (nominal) November 2012"
  rect 1.372x0.71 smd paste-0.4: 1(-2.776,1.905) 2(-2.776,0.635) 3(-2.776,-0.635) 4(-2.776,-1.905)
  rect 0.59x0.71 smd paste-0.3: 5(2.776,-1.905) 6(2.776,-0.635) 7(2.776,0.635) 8(2.776,1.905)
  Top Layer region: -1.106,-2.26 2.744,-2.26 2.744,2.26 -1.106,2.26
  silkscreen extent -3.38,-2.7 3,2.7, body extent -3.23,-2.55 2.87,2.55, height 1.06
TRANS_NexFET_Q5B#2 [mm] "TI recommended land pattern (nominal) November 2012"
  rect 1.372x0.71 smd paste-0.4 mask+0.051: 1(-2.776,1.905) 2(-2.776,0.635) 3(-2.776,-0.635) 4(-2.776,-1.905)
  rect 0.59x0.71 smd paste-0.3: 5(2.776,-1.905) 6(2.776,-0.635) 7(2.776,0.635) 8(2.776,1.905)
  Top Layer region: -1.106,-2.26 2.744,-2.26 2.744,2.26 -1.106,2.26
  body extent -3.23,-2.55 2.87,2.55, height 1.06
TSW-104-07-G-S [mm] "Samtec 100mil, 1x4, 230 mil above insulator"
  rect 1.65x1.65 hole 1.016 mask+0: 1(-3.81,0)
  round 1.65 hole 1.016 mask+0: 2(-1.27,0) 3(1.27,0) 4(3.81,0)
  silkscreen extent -6.1,-1.27 5.08,1.27, body extent -5.08,-1.27 5.08,1.27, height 8.38
XAL1580 [mm] "COILCRAFT"
  rect 3.18x14.36 smd: 1(-5.3,0) 2(5.3,0)
  silkscreen extent -7.7,-7.8 7.7,7.8, body extent -7.71,-7.81 7.71,7.81, height 8
XFMR_12X12.5-8P [mm]
  rect 2.3x1 smd: 1(-5.65,3) 2(-5.65,1) 3(-5.65,-1) 4(-5.65,-3) 5(5.65,-3) 6(5.65,-1) 7(5.65,1) 8(5.65,3)
  silkscreen extent -6.65,5.13 -5.63,6.13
